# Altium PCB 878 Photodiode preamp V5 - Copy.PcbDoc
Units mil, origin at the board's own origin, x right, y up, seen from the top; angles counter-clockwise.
Board outline 4488 x 4488 mil, 6 copper layers (Top Layer, Internal Plane 1, Dummy Ground, Dummy Power, Internal Plane 2, Bottom Layer), stack 21.034 mil thick; 182 components, 80 nets, 485 pads, 78 vias.
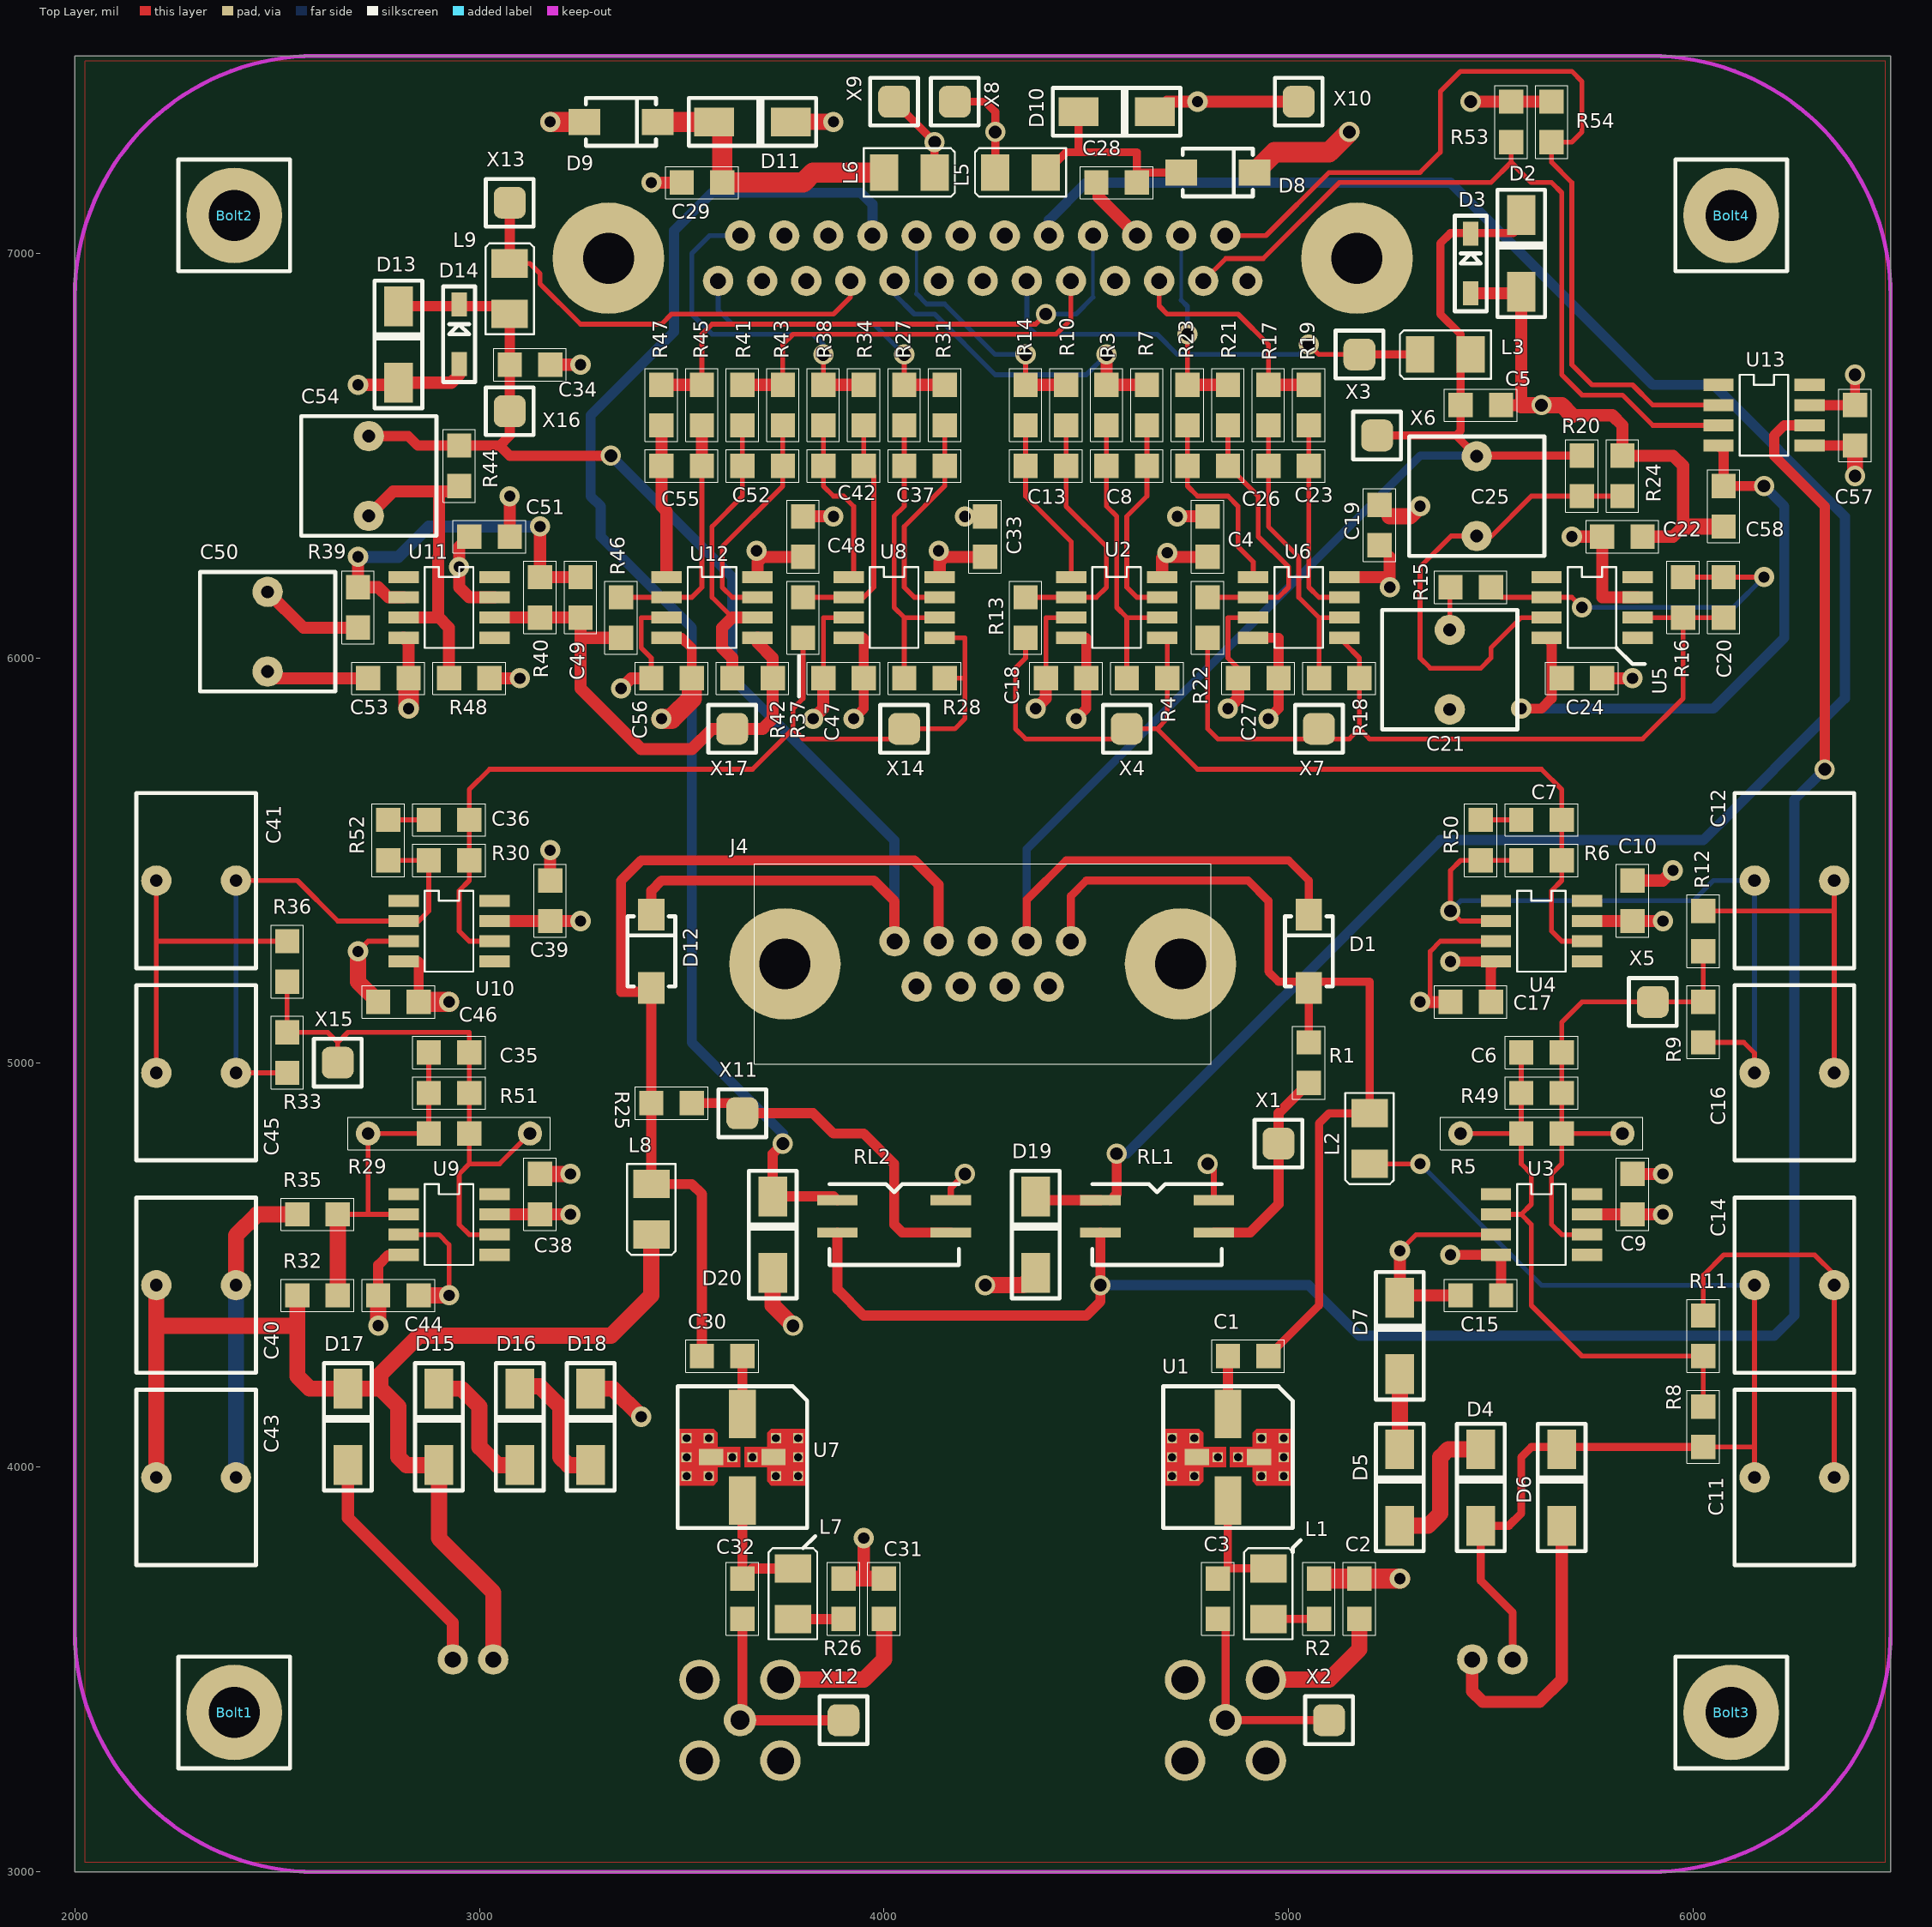
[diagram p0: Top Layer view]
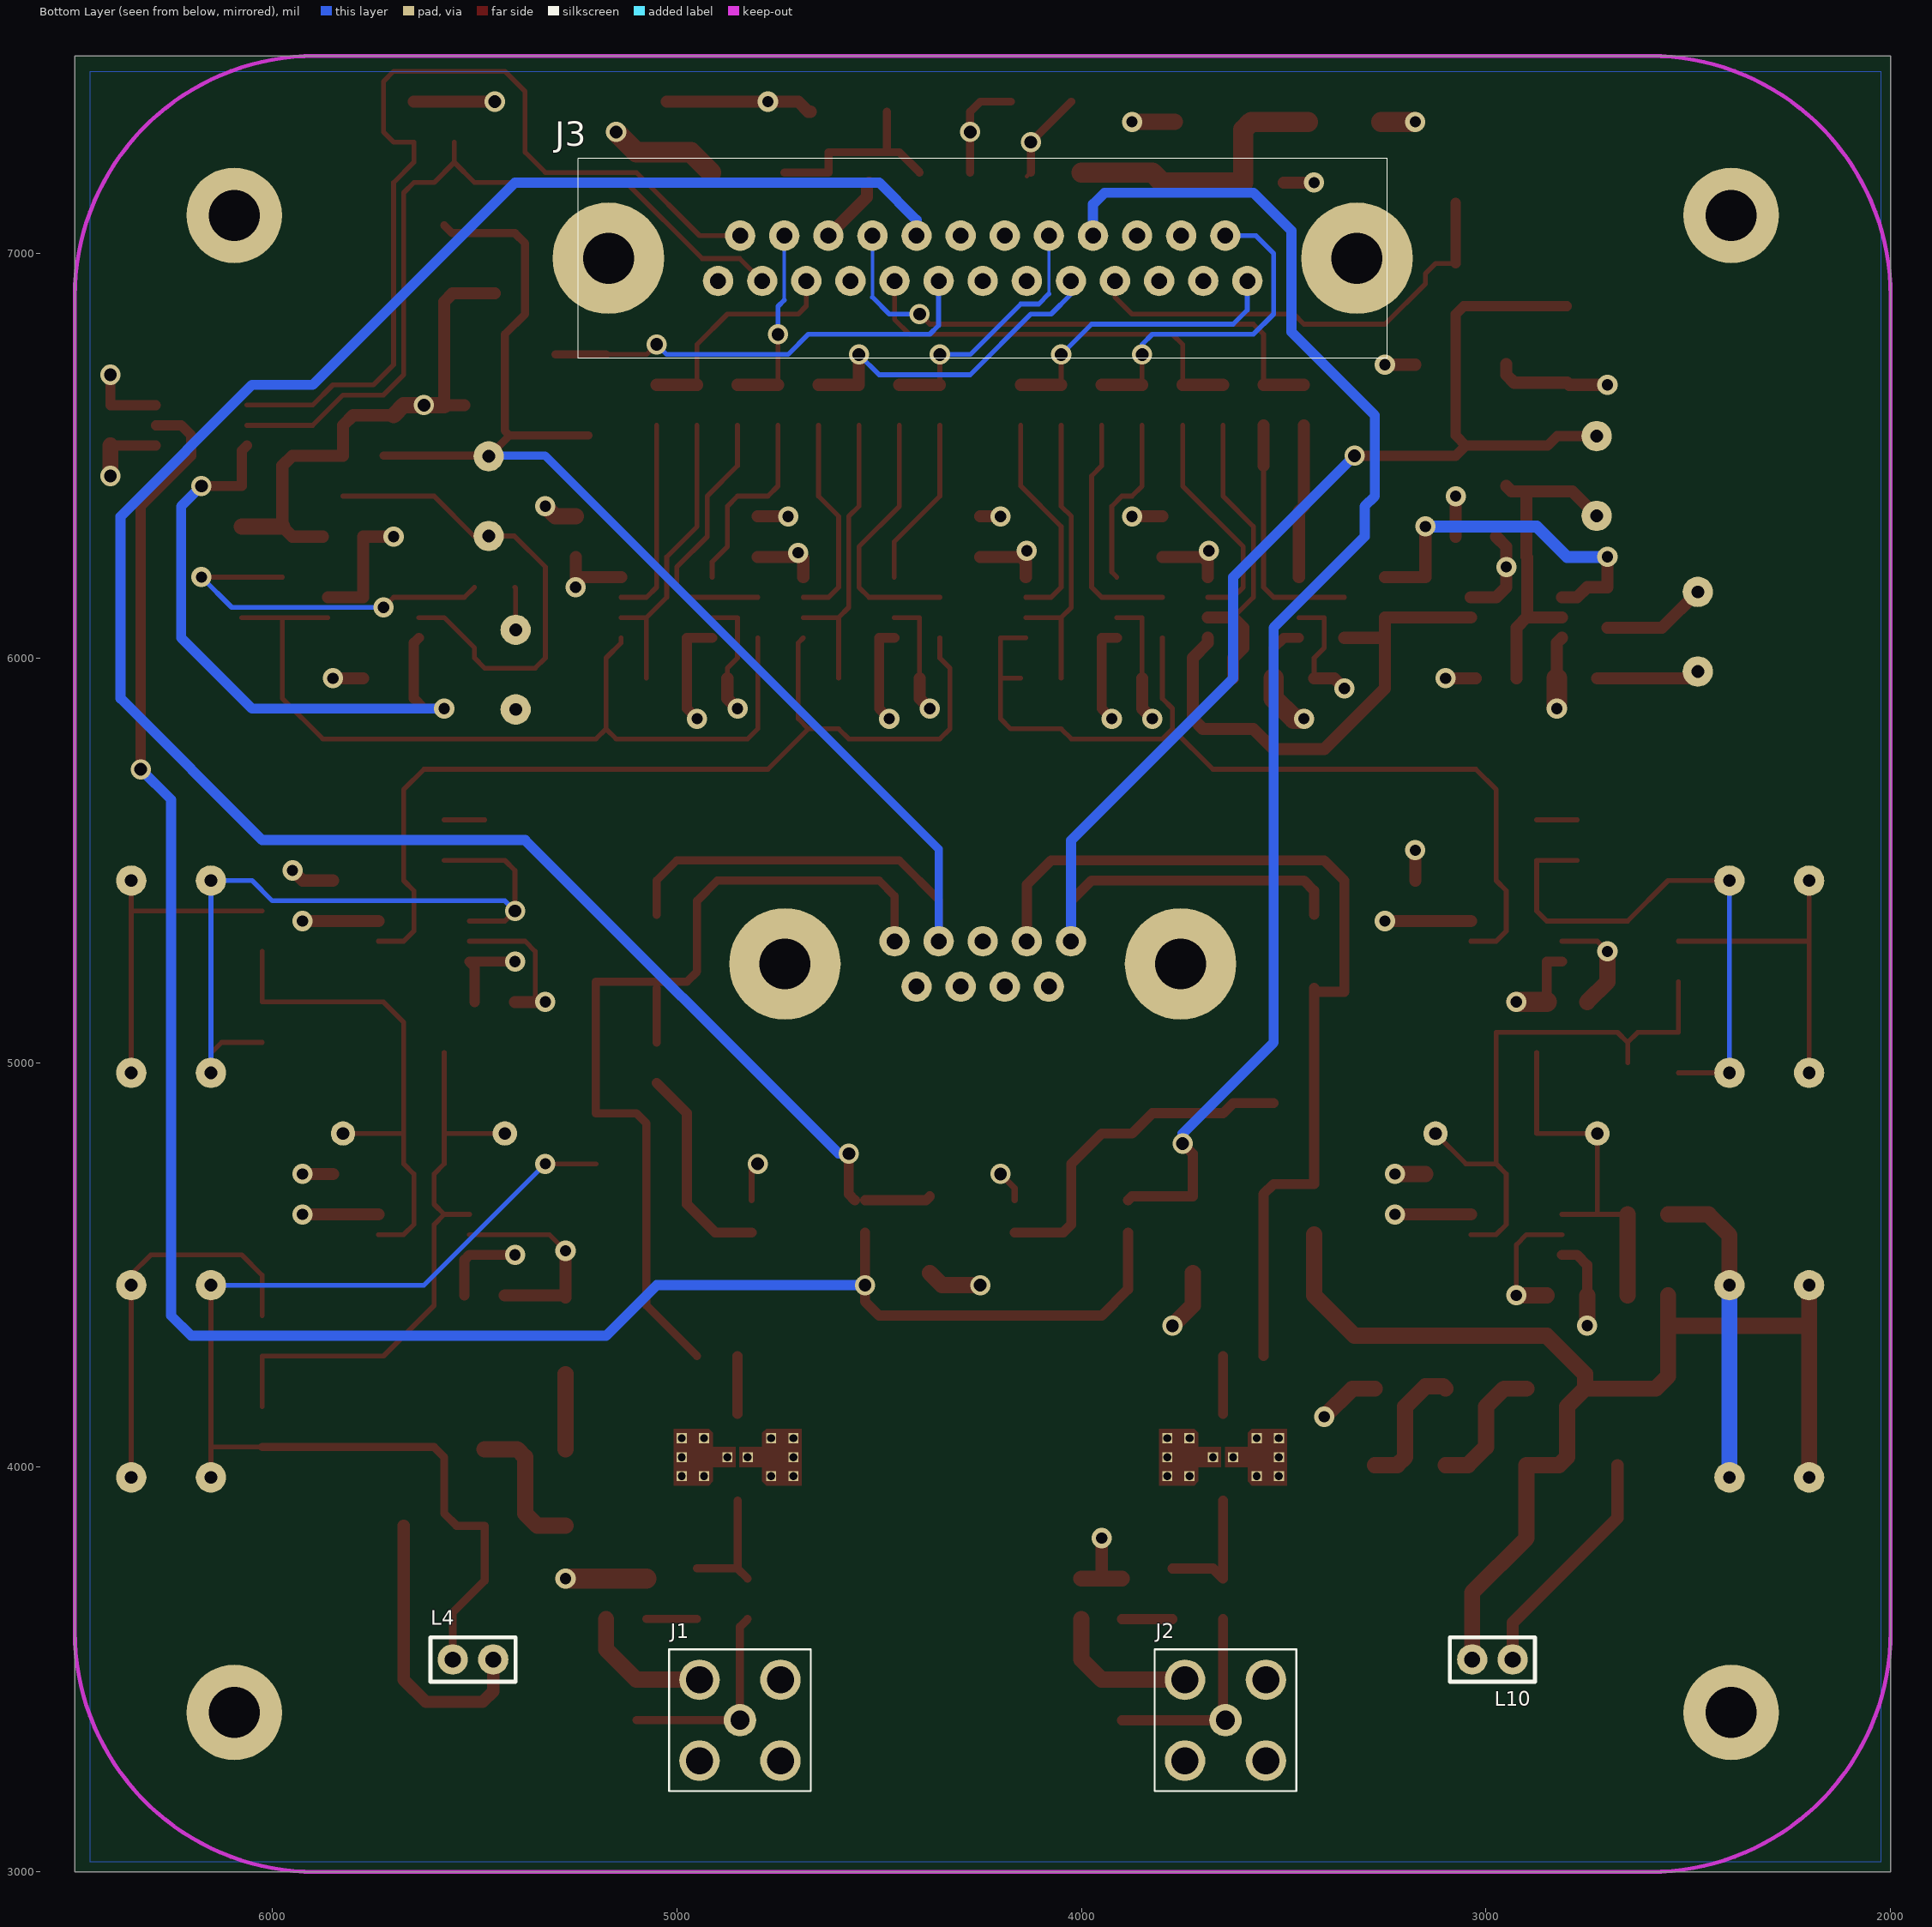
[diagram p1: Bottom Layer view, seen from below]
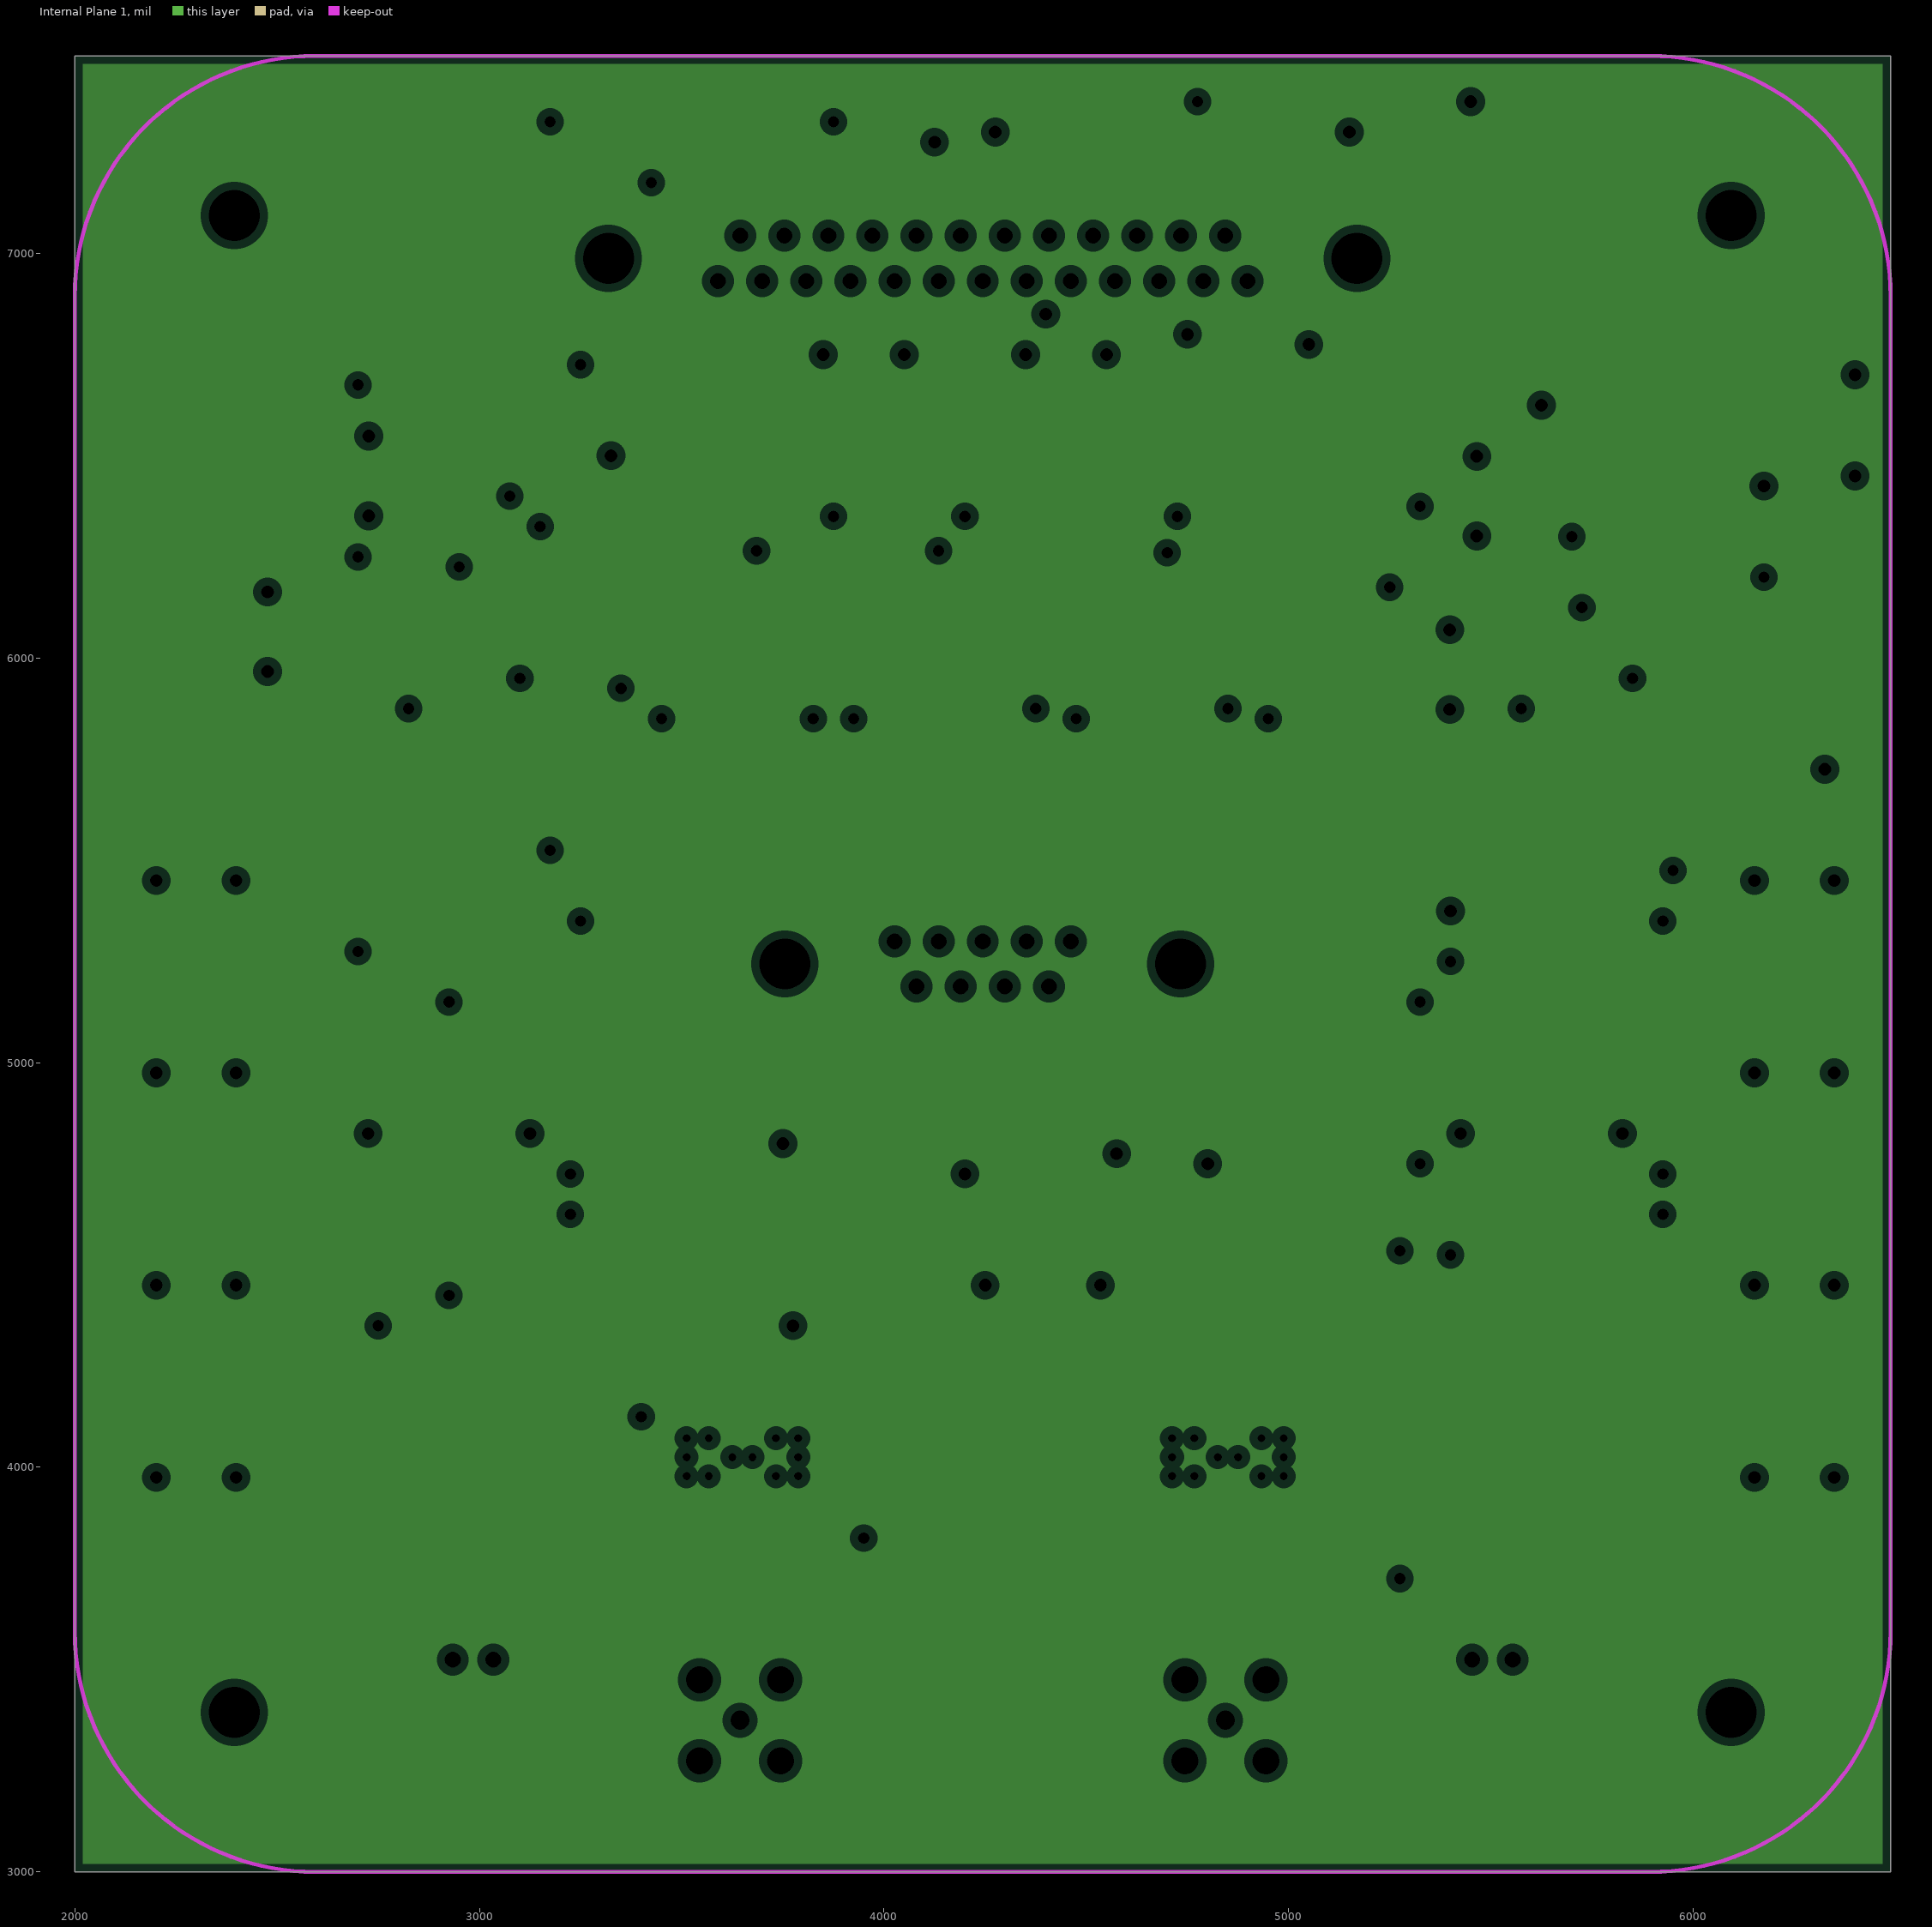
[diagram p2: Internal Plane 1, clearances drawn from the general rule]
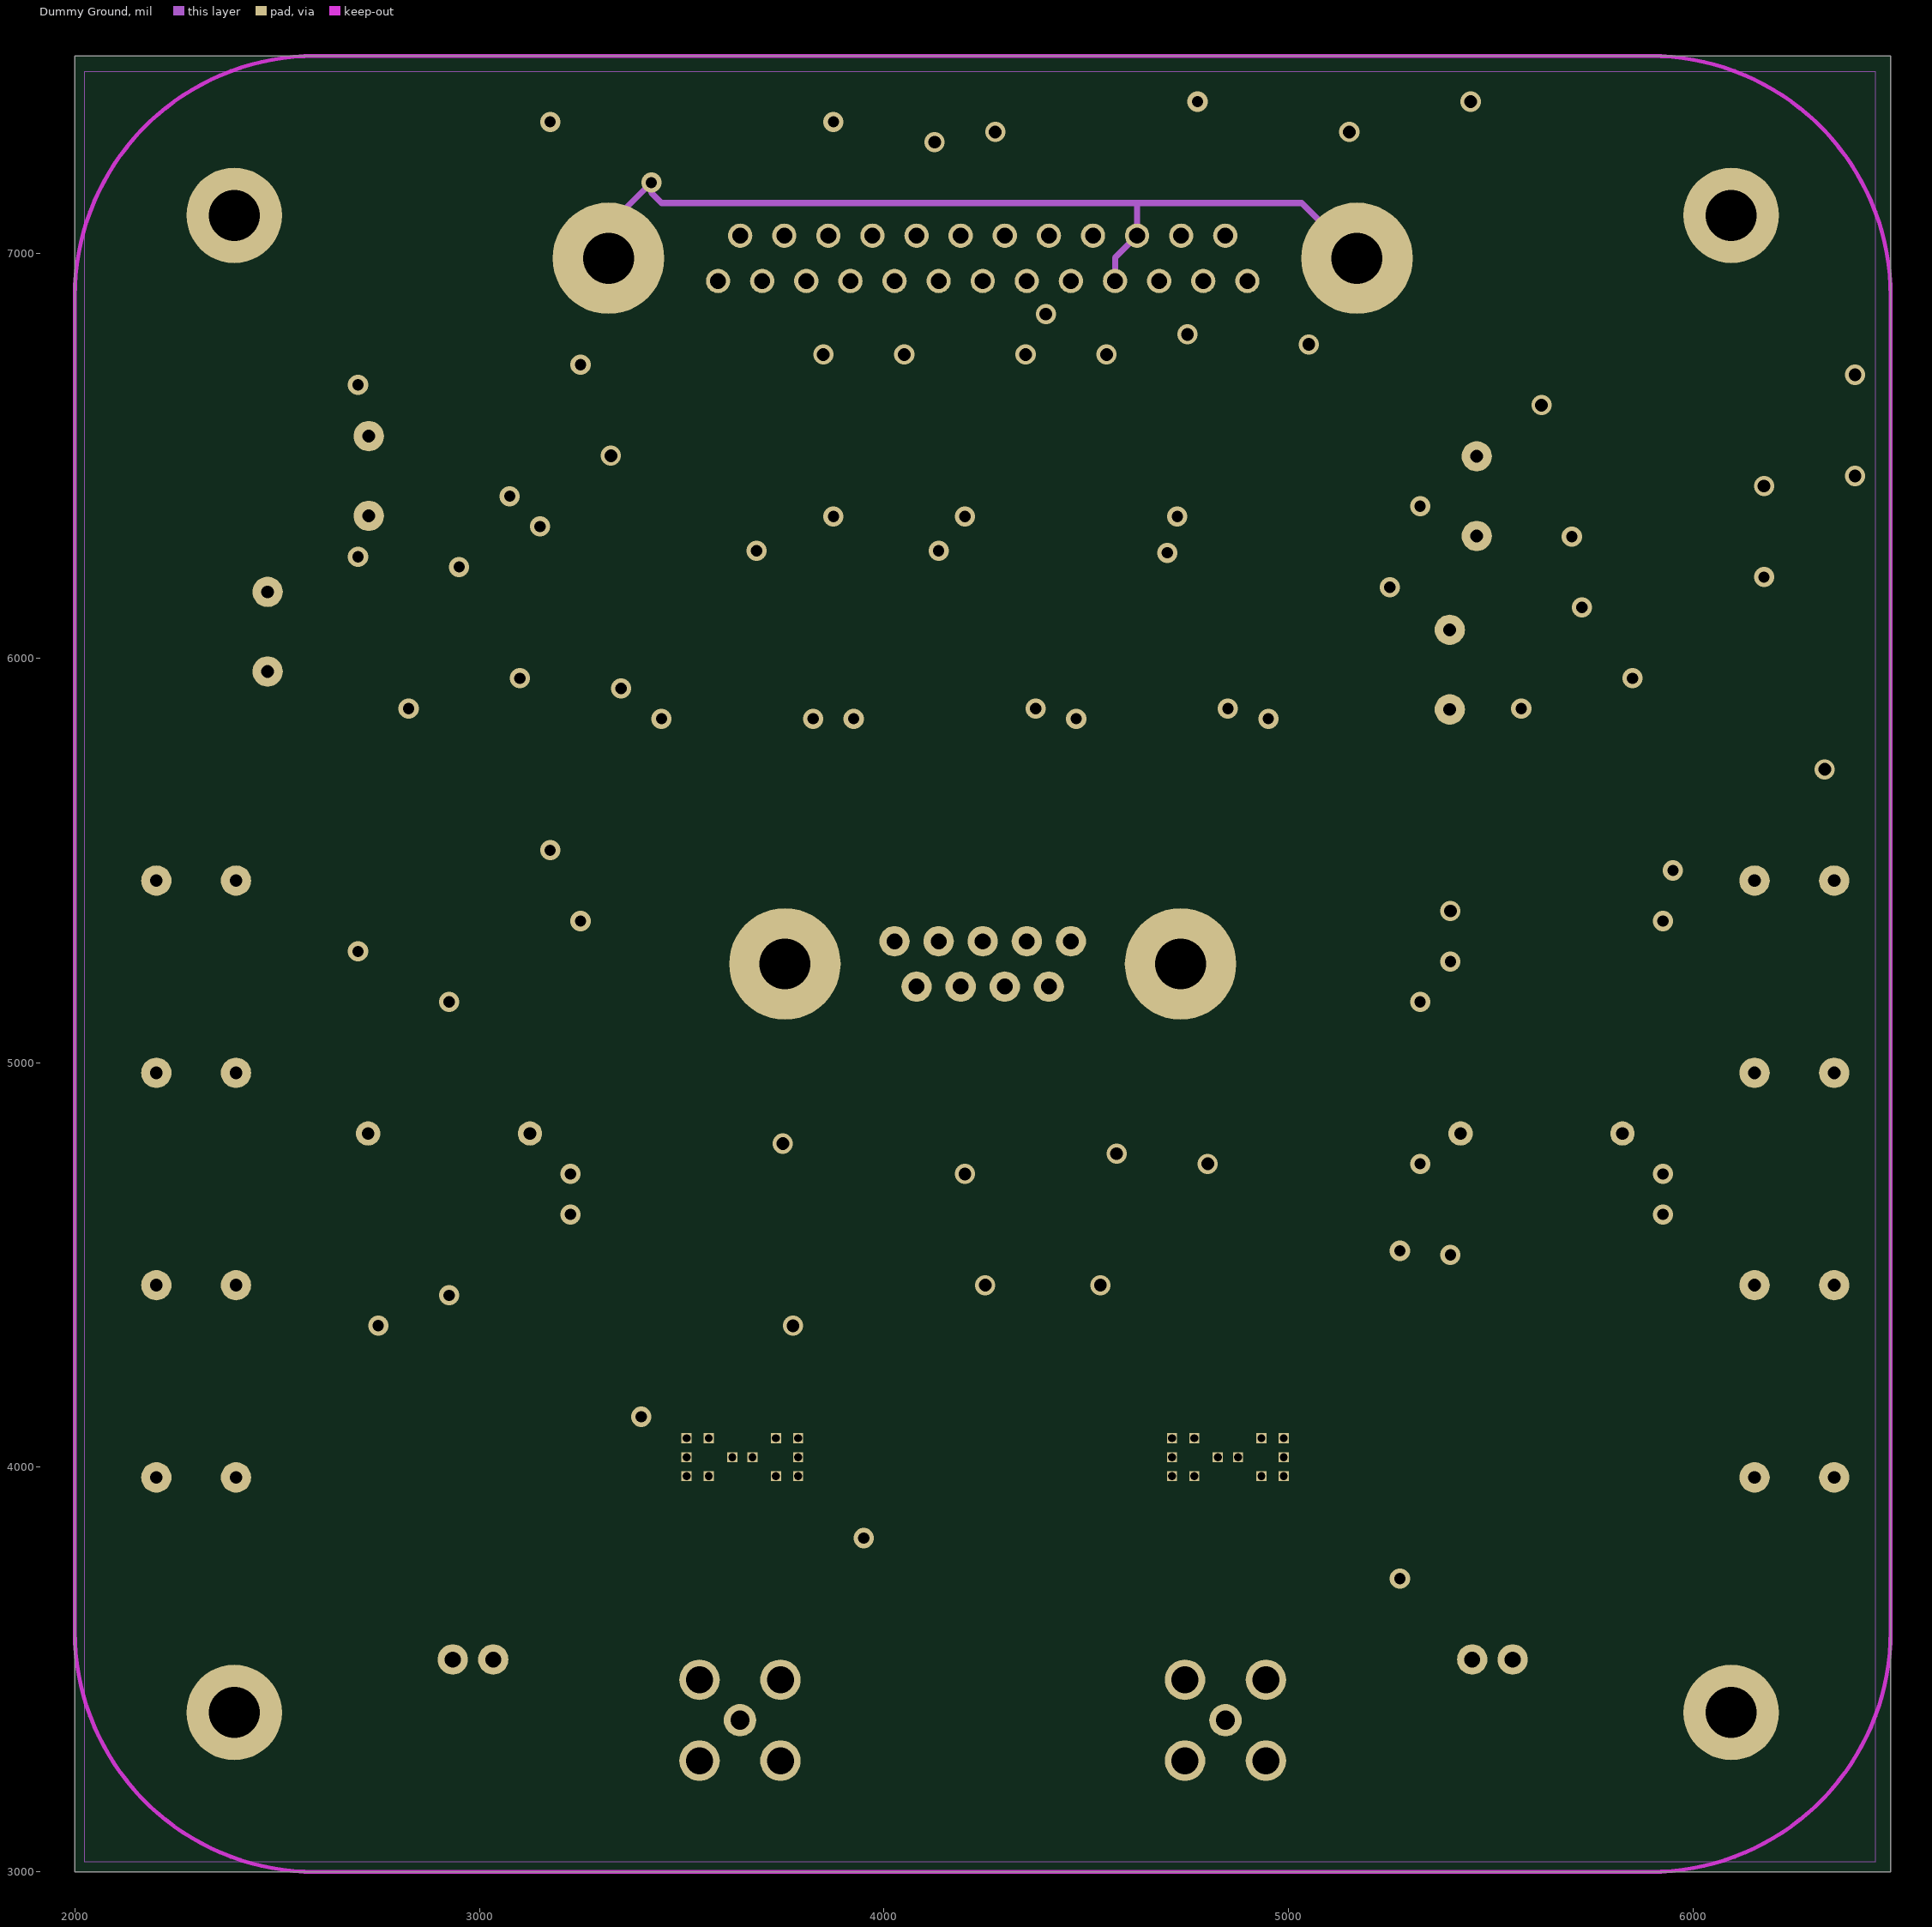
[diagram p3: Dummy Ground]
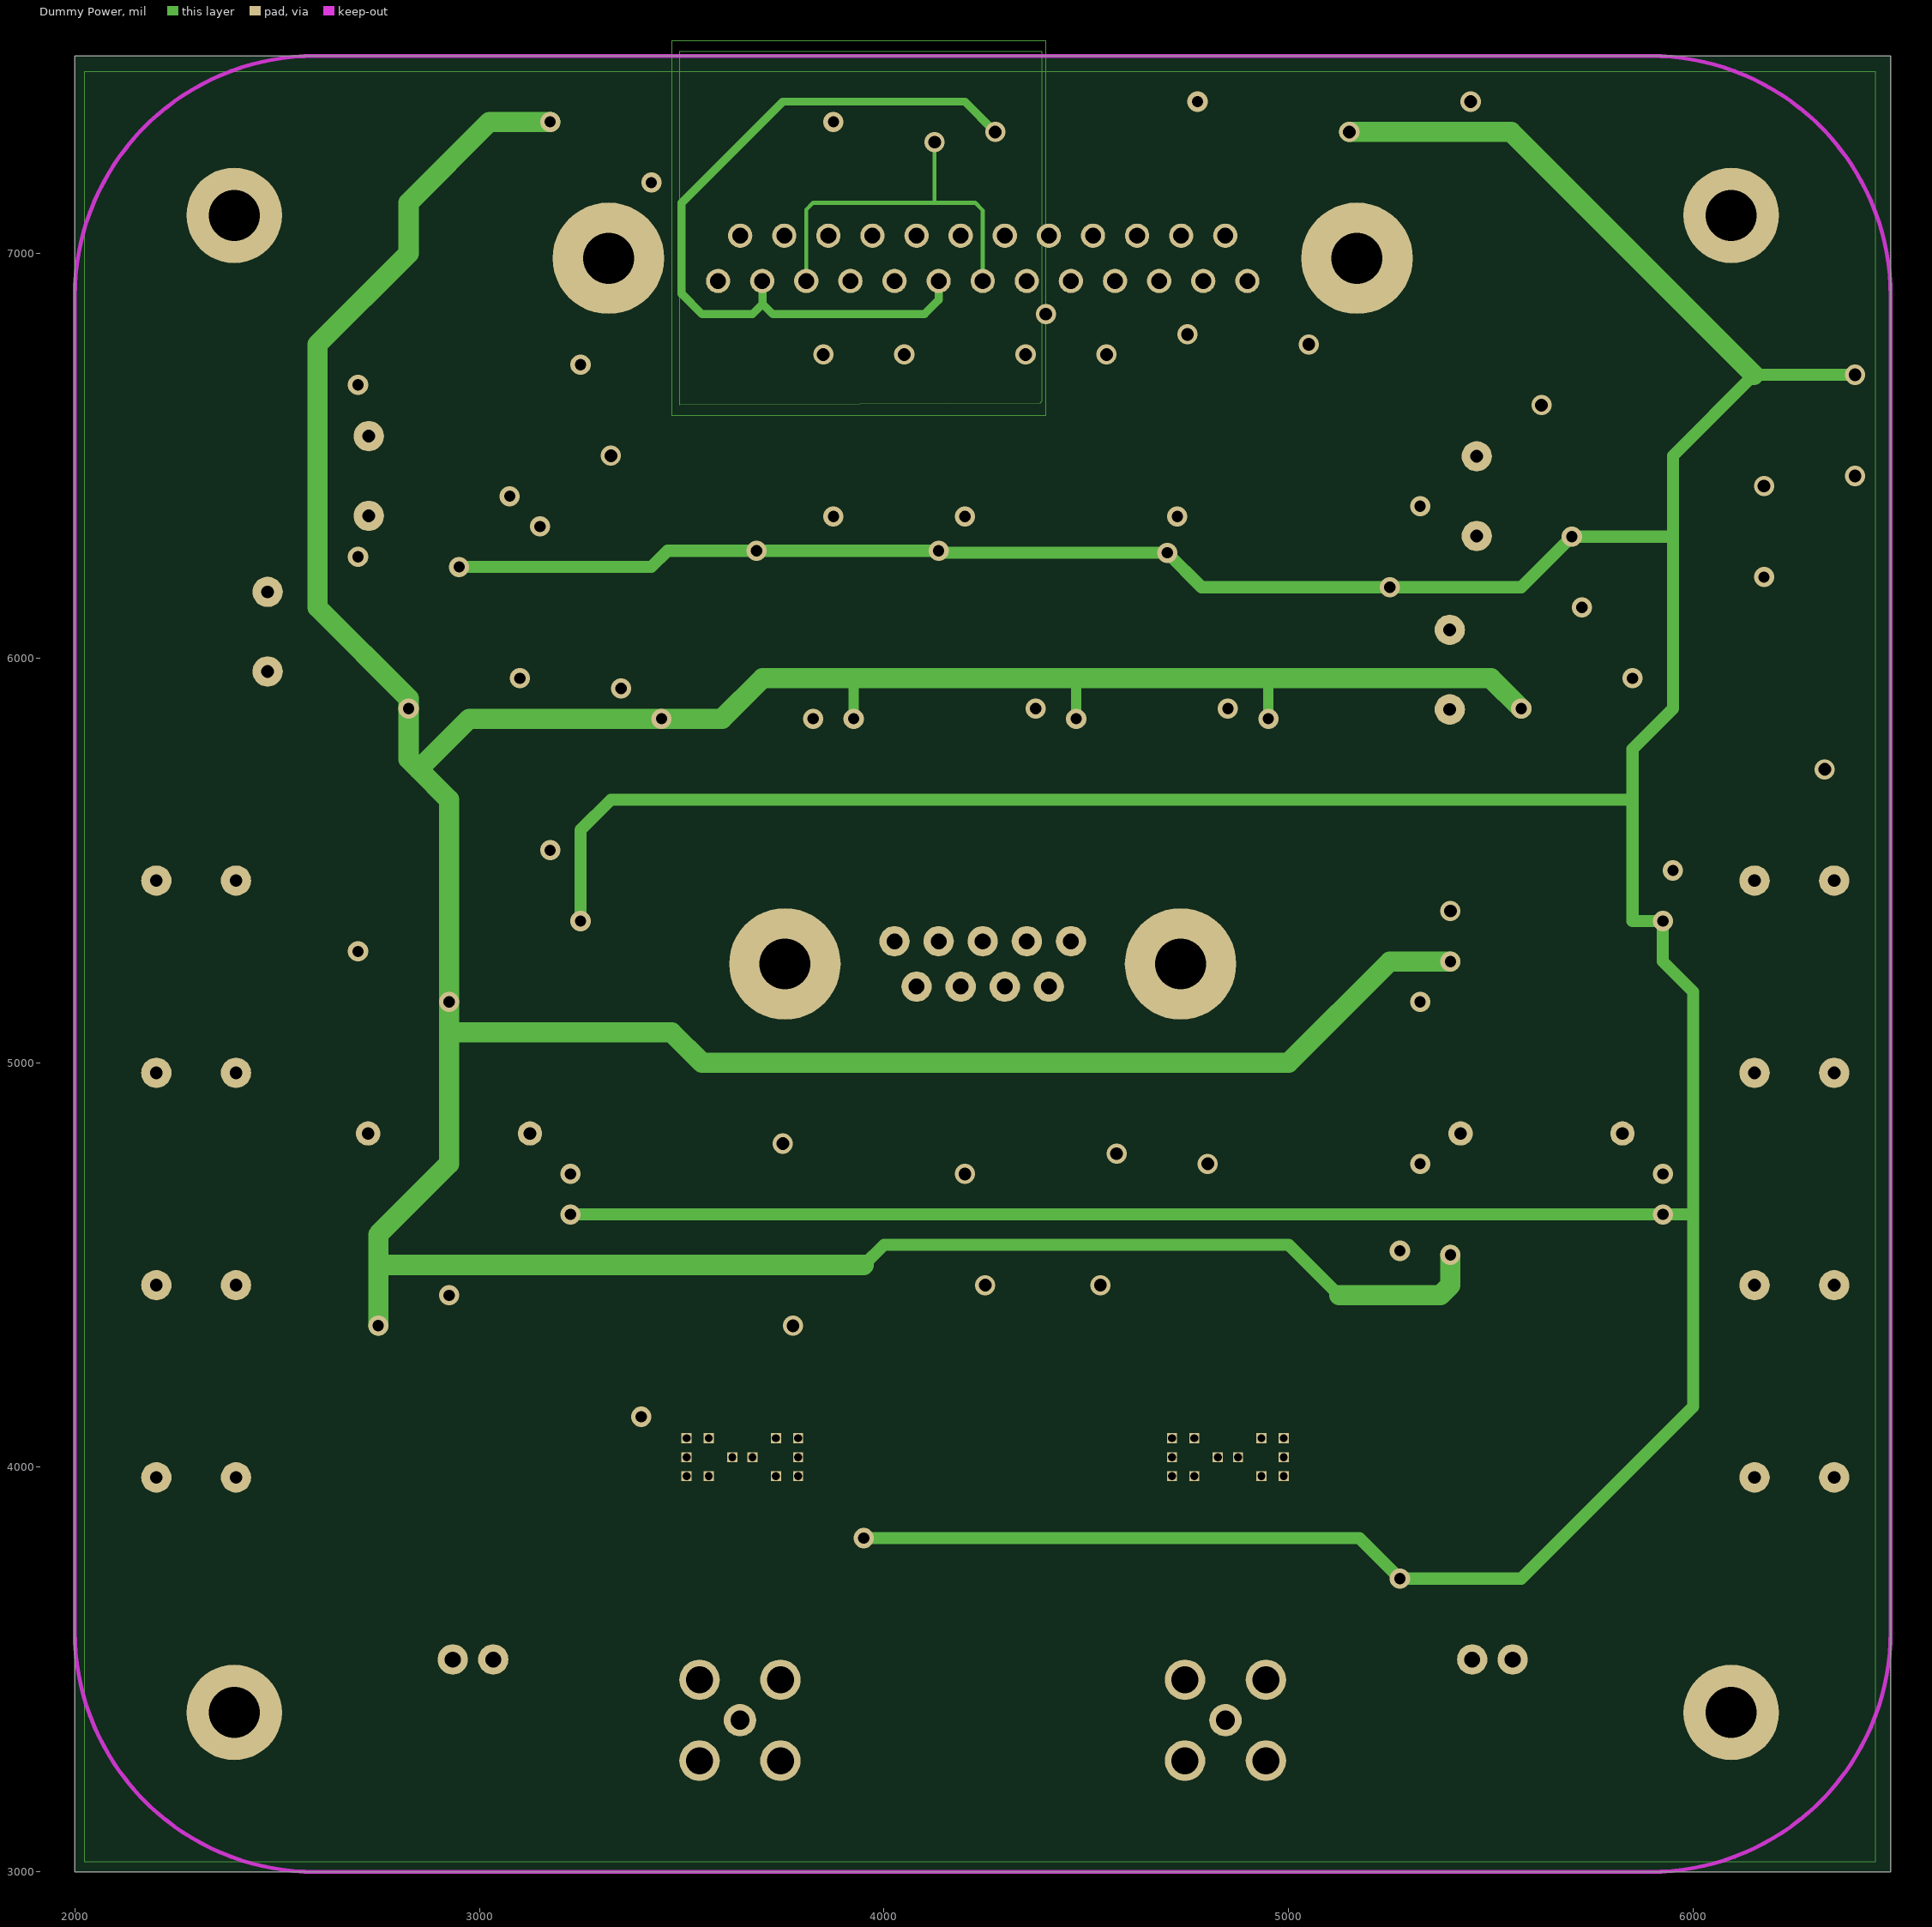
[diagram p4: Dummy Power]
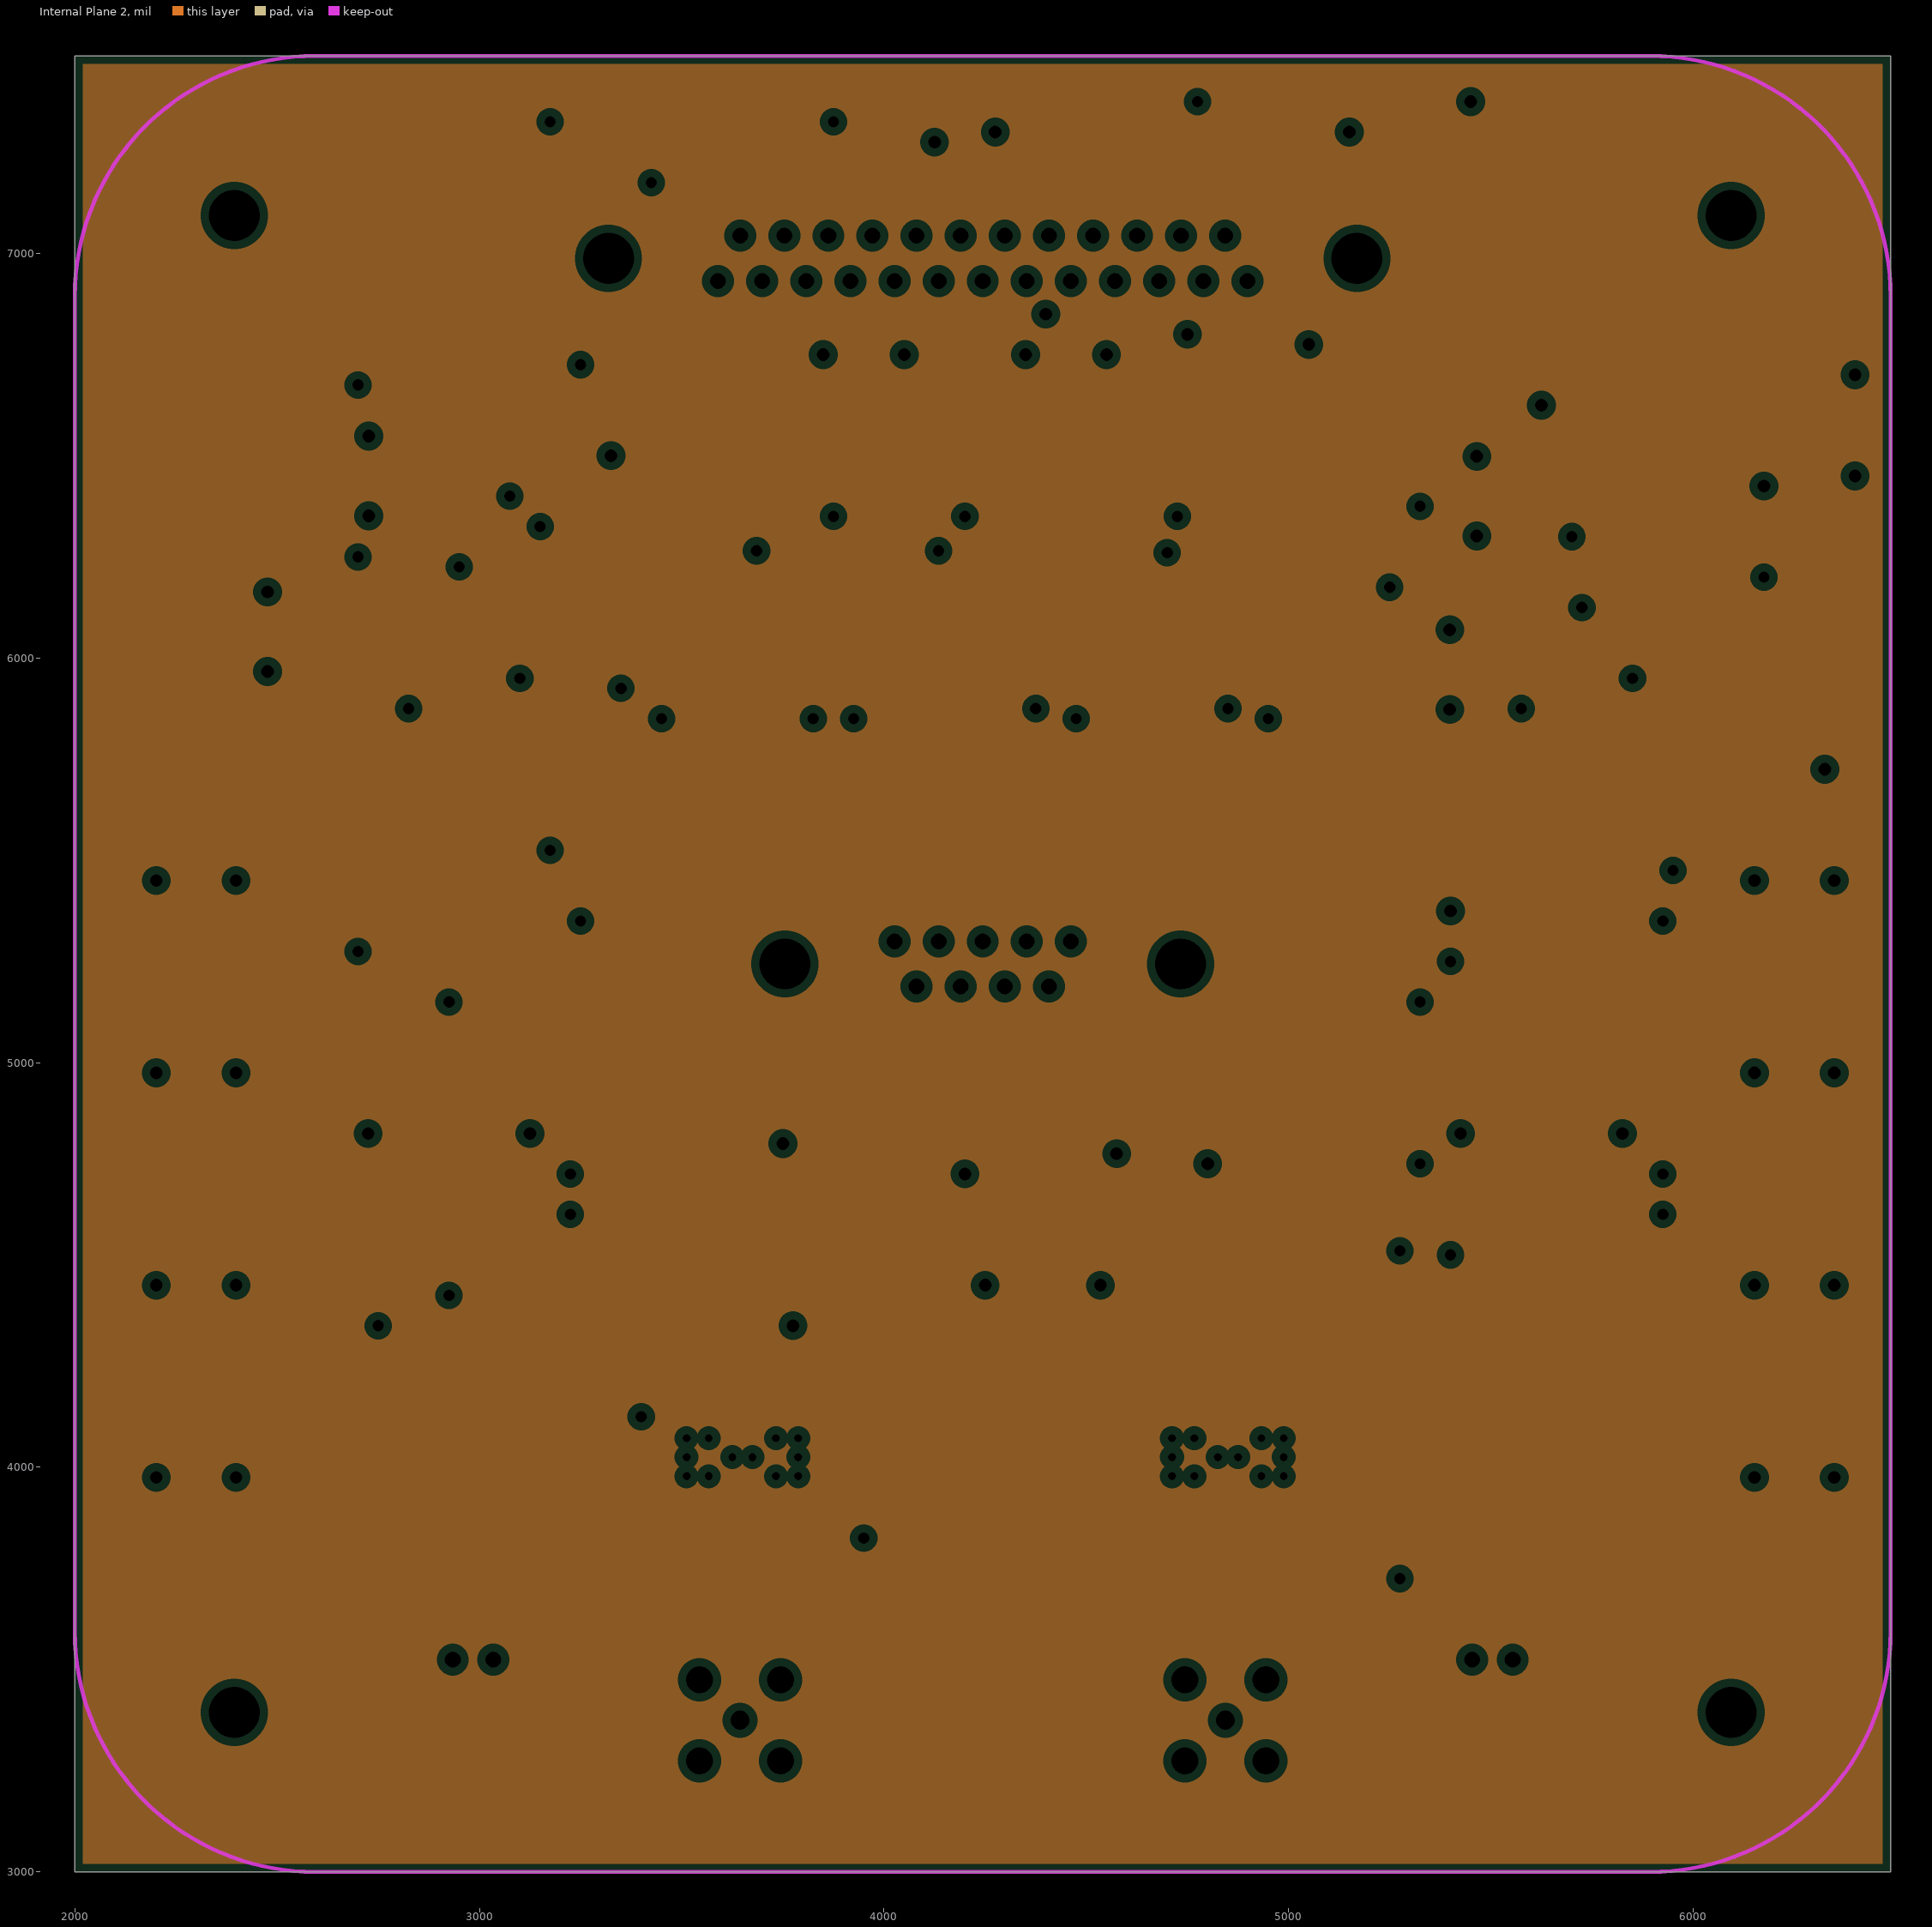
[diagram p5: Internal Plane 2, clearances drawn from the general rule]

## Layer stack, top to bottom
Top Solder: solder mask 0.4, Solder Resist, Dk 3.5
Top Layer: signal copper 1.4
Internal Plane 1: plane copper 1.4
Dummy Ground: signal copper 1.417
Dummy Power: signal copper 1.417
Internal Plane 2: plane copper 1.4
Dielectric 1: dielectric 12.6, FR-4, Dk 4.8
Bottom Layer: signal copper 1.4
Bottom Solder: solder mask 0.4, Solder Resist, Dk 3.5

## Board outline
2000,3000 6488,3000 6488,7488 2000,7488

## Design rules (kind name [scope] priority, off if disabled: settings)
Clearance Clearance_2 [InNamedPolygon('Top Layer-GND')] p1: gap=50
Clearance Clearance_1 [(InNamedPolygon('Top Layer-No Net'))] p2: gap=20
Clearance [All] p3: gap=12 except(8: Track-SMDPad)
HoleSize [All] p1: absolutevalues=TRUE maxlimit=150 minlimit=1 maxpercent=80.000 minpercent=20.000
PlaneClearance [All] p1: clearance=20
PlaneConnect [All] p1: planeconnectstyle=Relief reliefexpansion=20 reliefentries=4 reliefconductorwidth=10 reliefairgap=10
PolygonConnect [All] p1: connectstyle=Relief reliefconductorwidth=10 reliefentries=4 polygonreliefangle="90 Angle" airgapwidth=10
RoutingVias [All] p1: holewidth=31.5 width=50 viastyle="Through Hole" minholewidth=19.68 minwidth=30 maxholewidth=31.5 maxwidth=60
SilkToSilkClearance [All] p1: silktosilkclearance=5
SilkToSolderMaskClearance [IsPad] p1: minsilkscreentomaskgap=3 clearancetoexposedcopper=TRUE
SolderMaskExpansion [All] p1: expansion=4
Width [All] p1: maxlimit=200 minlimit=6 preferedwidth=12
25 further rules are at their usual default settings.

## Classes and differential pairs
component class "878 Photodiode preamp v5 P2": C30 C31 C32 C33 C34 C35 C36 C37 C38 C39 C40 C41 C42 C43 C44 C45 C46 C47 C48 C49 C50 C51 C52 C53 C54 C55 C56 D12 D13 D14 D15 D16 D17 D18 D20 J2 J3 J4 L7 L8 L9 L10 R25 R26 R27 R28 R29 R30 R31 R32 R33 R34 R35 R36 R37 R38 R39 R40 R41 R42 R43 R44 R45 R46 R47 R48 R51 R52 RL2 U7 U8 U9 U10 U11 U12 X11 X12 X13 X14 X15 X16 X17
component class "878 Photodiode preamp v5 P1": Bolt1 Bolt2 Bolt3 Bolt4 C1 C2 C3 C4 C5 C6 C7 C8 C9 C10 C11 C12 C13 C14 C15 C16 C17 C18 C19 C20 C21 C22 C23 C24 C25 C26 C27 C28 C29 C57 C58 D1 D2 D3 D4 D5 D6 D7 D8 D9 D10 D11 D19 J1 L1 L2 L3 L4 L5 L6 R1 R2 R3 R4 R5 R6 R7 R8 R9 R10 R11 R12 R13 R14 R15 R16 R17 R18 R19 R20 R21 R22 R23 R24 R49 R50 R53 R54 RL1 U1 U2 U3 U4 U5 U6 U13 X1 X2 X3 X4 X5 X6 X7 X8 X9 X10

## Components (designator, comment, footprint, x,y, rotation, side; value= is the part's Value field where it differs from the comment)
Bolt1 "Bolt M3" BOLT 2394,3394 r0 top
Bolt2 "Bolt M3" BOLT 2394,7094 r0 top
Bolt3 "Bolt M3" BOLT 6094,3394 r0 top
Bolt4 "Bolt M3" BOLT 6094,7094 r0 top
C1 "Cap200" HS0805Long 4900,4275 r180 top
C2 "Cap200" HS0805Long 5175,3675 r270 top
C3 "Cap200" HS0805Long 4825,3675 r270 top
C4 "Cap200" HS0805Long 4800,6300 r90 top
C5 "Cap200" HS0805Long 5475,6625 r0 top
C6 "Cap200" HS0805Long 5625,5025 r0 top
C7 "Cap200" HS0805Long 5625,5600 r0 top
C8 "Cap200" HS0805Long 4600,6475 r0 top
C9 "Cap200" HS0805Long 5850,4675 r90 top
C10 "Cap200" HS0805Long 5850,5400 r90 top
C11 "Cap200" "MKS2 7.2 11" 6250,3975 r0 top
C12 "Cap200" "MKS2 7.2 11" 6250,5450 r180 top
C13 "Cap200" HS0805Long 4400,6475 r180 top
C14 "Cap200" "MKS2 7.2 11" 6250,4450 r0 top
C15 "Cap200" HS0805Long 5475,4425 r180 top
C16 "Cap200" "MKS2 7.2 11" 6250,4975 r180 top
C17 "Cap200" HS0805Long 5450,5150 r180 top
C18 "Cap200" HS0805Long 4450,5950 r180 top
C19 "Cap200" HS0805Long 5225,6328.51 r90 top
C20 "Cap200" HS0805Long 6075,6150 r270 top
C21 "Cap200" "MKS2 7.2 8.5" 5398.33,5971.35 r90 top
C22 "Cap200" HS0805Long 5825,6300 r0 top
C23 "Cap200" HS0805Long 5000,6475 r0 top
C24 "Cap200" HS0805Long 5725,5950 r0 top
C25 "Cap200" "MKS2 7.2 8.5" 5465.07,6400 r270 top
C26 "Cap200" HS0805Long 4800,6475 r180 top
C27 "Cap200" HS0805Long 4925,5950 r180 top
C28 "Cap200" HS0805Long 4575,7175 r180 top
C29 "Cap200" HS0805Long 3550,7175 r180 top
C30 "Cap200" HS0805Long 3600,4275 r0 top
C31 "Cap200" HS0805Long 4000,3675 r270 top
C32 "Cap200" HS0805Long 3650,3675 r270 top
C33 "Cap200" HS0805Long 4250,6300 r90 top
C34 "Cap200" HS0805Long 3125,6725 r0 top
C35 "Cap200" HS0805Long 2925,5025 r0 top
C36 "Cap200" HS0805Long 2925,5600 r0 top
C37 "Cap200" HS0805Long 4100,6475 r0 top
C38 "Cap200" HS0805Long 3150,4675 r90 top
C39 "Cap200" HS0805Long 3175,5400 r90 top
C40 "Cap200" "MKS2 7.2 11" 2300,4450 r0 top
C41 "Cap200" "MKS2 7.2 11" 2300,5450 r0 top
C42 "Cap200" HS0805Long 3900,6475 r180 top
C43 "Cap200" "MKS2 7.2 11" 2300,3975 r0 top
C44 "Cap200" HS0805Long 2800,4425 r0 top
C45 "Cap200" "MKS2 7.2 11" 2300,4975 r0 top
C46 "Cap200" HS0805Long 2800,5150 r180 top
C47 "Cap200" HS0805Long 3900,5950 r180 top
C48 "Cap200" HS0805Long 3800,6300 r90 top
C49 "Cap200" HS0805Long 3250,6150 r270 top
C50 "Cap200" "MKS2 7.2 8.5" 2476.67,6065 r90 top
C51 "Cap200" HS0805Long 3025,6300 r0 top
C52 "Cap200" HS0805Long 3700,6475 r0 top
C53 "Cap200" HS0805Long 2775,5950 r180 top
C54 "Cap200" "MKS2 7.2 8.5" 2726.67,6449.87 r270 top
C55 "Cap200" HS0805Long 3500,6475 r180 top
C56 "Cap200" HS0805Long 3475,5950 r180 top
C57 "Cap200" HS0805Long 6400,6575 r90 top
C58 "Cap200" HS0805Long 6075,6375 r270 top
D1 "60V 1A" SMA 5050,5275 r270 top
D2 "SMAJxxCA" DO214AC 5575,7000 r270 top
D3 "60V 1A" SOD123 5450,6975 r270 top
D4 "1N4007" DO214AC 5475,3950 r270 top
D5 "1N4007" DO214AC 5275,3950 r270 top
D6 "1N4007" DO214AC 5675,3950 r270 top
D7 "1N4007" DO214AC 5275,4325 r270 top
D8 "60V 1A" SMA 4825,7200 r180 top
D9 "60V 1A" SMA 3350,7325 r180 top
D10 "SMAJxxCA" DO214AC 4575,7350 r180 top
D11 "SMAJxxCA" DO214AC 3675,7325 r180 top
D12 "60V 1A" SMA 3425,5275 r270 top
D13 "SMAJxxCA" DO214AC 2800,6775 r270 top
D14 "60V 1A" SOD123 2950,6800 r270 top
D15 "1N4007" DO214AC 2900,4100 r270 top
D16 "1N4007" DO214AC 3100,4100 r270 top
D17 "1N4007" DO214AC 2675,4100 r270 top
D18 "1N4007" DO214AC 3275,4100 r270 top
D19 "1N4004" DO214AC 4375,4575 r270 top
D20 "1N4004" DO214AC 3725,4575 r270 top
J1 "SMA" "PCB SMB" 4844,3375 r180 bottom
J2 "SMA" "PCB SMB" 3644,3375 r180 bottom
J3 "D connector 25 way" "D Socket Straight PCB 25 Way" 4244,6987.81 r0 bottom
J4 "D connector 9 way" "D Plug Straight PCB 9 Way" 4244,5244 r0 top
L1 "Inductor" HS1210 4950,3700 r270 top
L2 "Inductor" HS1210 5200,4800 r90 top
L3 "Inductor" HS1210 5375,6750 r0 top
L4 "Inductor" "2 way 0.1\"" 5503.75,3525 r0 bottom
L5 "Inductor" HS1210 4325,7200 r0 top
L6 "Inductor" HS1210 4075,7200 r180 top
L7 "Inductor" HS1210 3775,3700 r270 top
L8 "Inductor" HS1210 3425,4625 r90 top
L9 "Inductor" HS1210 3075,6925 r270 top
L10 "Inductor" "2 way 0.1\"" 2984.25,3525 r0 bottom
R1 "Res" hs0805long 5050,5000 r90 top
R2 "Res" hs0805long 5075,3675 r90 top
R3 "Res" hs0805long 4550,6625 r90 top
R4 "Res" hs0805long 4650,5950 r180 top
R5 "Res" SpecialR 5625,4825 r0 top
R6 "Res" hs0805long 5625,5500 r0 top
R7 "Res" hs0805long 4650,6625 r90 top
R8 "Res" hs0805long 6025,4100 r90 top
R9 "Res" hs0805long 6025,5100 r270 top
R10 "Res" hs0805long 4450,6625 r90 top
R11 "Res" hs0805long 6025,4325 r270 top
R12 "Res" hs0805long 6025,5325 r90 top
R13 "Res" hs0805long 4350,6100 r90 top
R14 "Res" hs0805long 4350,6625 r90 top
R15 "Res" hs0805long 5450,6175 r180 top
R16 "Res" hs0805long 5975,6150 r270 top
R17 "Res" hs0805long 4950,6625 r90 top
R18 "Res" hs0805long 5125,5950 r180 top
R19 "Res" hs0805long 5050,6625 r90 top
R20 "Res" hs0805long 5725,6450 r90 top
R21 "Res" hs0805long 4850,6625 r90 top
R22 "Res" hs0805long 4800,6100 r90 top
R23 "Res" hs0805long 4750,6625 r90 top
R24 "Res" hs0805long 5825,6450 r270 top
R25 "Res" hs0805long 3475,4900 r180 top
R26 "Res" hs0805long 3900,3675 r90 top
R27 "Res" hs0805long 4050,6625 r90 top
R28 "Res" hs0805long 4100,5950 r180 top
R29 "Res" SpecialR 2925,4825 r0 top
R30 "Res" hs0805long 2925,5500 r0 top
R31 "Res" hs0805long 4150,6625 r90 top
R32 "Res" hs0805long 2600,4425 r0 top
R33 "Res" hs0805long 2525,5025 r270 top
R34 "Res" hs0805long 3950,6625 r90 top
R35 "Res" hs0805long 2600,4625 r0 top
R36 "Res" hs0805long 2525,5250 r90 top
R37 "Res" hs0805long 3800,6100 r90 top
R38 "Res" hs0805long 3850,6625 r90 top
R39 "Res" hs0805long 2700,6125 r270 top
R40 "Res" hs0805long 3150,6150 r270 top
R41 "Res" hs0805long 3650,6625 r90 top
R42 "Res" hs0805long 3675,5950 r180 top
R43 "Res" hs0805long 3750,6625 r90 top
R44 "Res" hs0805long 2950,6475 r90 top
R45 "Res" hs0805long 3550,6625 r90 top
R46 "Res" hs0805long 3350,6100 r90 top
R47 "Res" hs0805long 3450,6625 r90 top
R48 "Res" hs0805long 2975,5950 r180 top
R49 "Res" hs0805long 5625,4925 r0 top
R50 "Res" hs0805long 5475,5550 r90 top
R51 "Res" hs0805long 2925,4925 r0 top
R52 "Res" hs0805long 2775,5550 r90 top
R53 "Res" HS0805Long 5550,7325 r270 top
R54 "Res" HS0805Long 5650,7325 r270 top
RL1 "9901 relay" "9901 Relay" 4675,4600 r0 top
RL2 "9901 relay" "9901 Relay" 4025,4600 r0 top
U1 "MAR-6SM" ww107 4850,4025 r180 top
U2 "AD8672ARZ" "SOIC 8" 4575,6125 r270 top
U3 "LT1028" "SOIC 8" 5625,4600 r270 top
U4 "LT1028" "SOIC 8" 5625,5325 r270 top
U5 "LT1028" "SOIC 8" 5750,6125 r270 top
U6 "AD8672ARZ" "SOIC 8" 5025,6125 r270 top
U7 "MAR-6SM" ww107 3650,4025 r180 top
U8 "AD8672ARZ" "SOIC 8" 4025,6125 r270 top
U9 "LT1028" "SOIC 8" 2925,4600 r270 top
U10 "LT1028" "SOIC 8" 2925,5325 r270 top
U11 "LT1028" "SOIC 8" 2925,6125 r270 top
U12 "AD8672ARZ" "SOIC 8" 3575,6125 r270 top
U13 "AD620" "SOIC 8" 6175,6600 r270 top
X1 "TestPoint" "SM Test point" 4975,4800 r0 top
X2 "TestPoint" "SM Test point" 5100,3375 r0 top
X3 "TestPoint" "SM Test point" 5175,6750 r90 top
X4 "TestPoint" "SM Test point" 4600,5825 r90 top
X5 "TestPoint" "SM Test point" 5900,5150 r90 top
X6 "TestPoint" "SM Test point" 5218.68,6550 r0 top
X7 "TestPoint" "SM Test point" 5075,5825 r0 top
X8 "TestPoint" "SM Test point" 4175,7375 r0 top
X9 "TestPoint" "SM Test point" 4025,7375 r0 top
X10 "TestPoint" "SM Test point" 5025,7375 r0 top
X11 "TestPoint" "SM Test point" 3650,4875 r0 top
X12 "TestPoint" "SM Test point" 3900,3375 r0 top
X13 "TestPoint" "SM Test point" 3075,7125 r0 top
X14 "TestPoint" "SM Test point" 4050,5825 r90 top
X15 "TestPoint" "SM Test point" 2650,5000 r90 top
X16 "TestPoint" "SM Test point" 3075,6609.93 r0 top
X17 "TestPoint" "SM Test point" 3625,5825 r0 top

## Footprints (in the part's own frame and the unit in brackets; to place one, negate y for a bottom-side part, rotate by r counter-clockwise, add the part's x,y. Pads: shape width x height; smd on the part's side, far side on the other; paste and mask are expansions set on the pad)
"2 way 0.1\"" [mm] "two wire component!"
  round 1.905 hole 1: 1(-1.27,0) 2(1.27,0)
  silkscreen extent -2.67,-1.4 2.67,1.4
"9901 Relay" [mil] "SM reed relay"
  rect 100x25 smd: 1(-140,60) 2(140,60) 5(-140,-20) 6(140,-20)
  silkscreen extent -160,-100 160,100
BOLT [mm] "M3 mounting bolt"
  round 6 hole 3.2: 1(0,0)
  silkscreen extent -3.5,-3.5 3.5,3.5
"D Plug Straight PCB 9 Way" [mil] "D Plug Straight PCB 9 Way"
  round 75 hole 39.37: 1(-218,56) 2(-109,56) 3(0,56) 4(109,56) 5(218,56) 6(-163.5,-56) 7(-54.5,-56) 8(54.5,-56) 9(163.5,-56)
  round 275.59 hole 125.98: 10(-489,0) 10(489,0)
  silkscreen extent -564,-247 564,247
"D Socket Straight PCB 25 Way" [mil] "D socket Straight PCB 25 Way"
  round 75 / inner round 60 / far side round 75 hole 39.37: 1(654,56) 2(545,56) 3(436,56) 4(327,56) 5(218,56) 6(109,56) 7(0,56) 8(-109,56) 9(-218,56) 10(-327,56) 11(-436,56) 12(-545,56) 13(-654,56) 14(599.5,-56) 15(490.5,-56) 16(381.5,-56) 17(272.5,-56) 18(163.5,-56) 19(54.5,-56) 20(-54.5,-56) 21(-163.5,-56) 22(-272.5,-56) 23(-381.5,-56) 24(-490.5,-56) 25(-599.5,-56)
  round 275.59 hole 125.98: 26(-925,0) 26(925,0)
  silkscreen extent -1000,-247 1000,247
DO214AC [mm] "DO214AC"
  rect 2.5x1.8 smd: 1(-2.4,0) 2(2.4,0)
  silkscreen extent -4,-1.5 4,1.5
HS0805Long [mil] "0805 on big pads for hand soldering will also take 1206"
  rect 60x60 smd: 1(-50,0) 2(50,0)
  silkscreen extent -90,-40 90,40
hs0805long [mil] "0805 on big pads for hand soldering will also take 1206"
  rect 60x60 smd: 1(-50,0) 2(50,0)
  silkscreen extent -90,-40 90,40
HS1210 [mil] "Tant case B (A will also fit!)"
  rect 70x90 smd: 1(-50,0) 2(75,0)
  silkscreen extent -100,-60 125,60
"MKS2 7.2 8.5" [mm] "MKS2 7.2 by 8.5"
  round 1.905 hole 0.8: 1(-2.5,0) 2(2.5,0)
  silkscreen extent -3.75,-4.25 3.75,4.25
"MKS2 7.2 11" [mm] "MKS2 7.2 by 11 by 16"
  round 1.905 hole 0.8: 1(-2.5,0) 2(2.5,0)
  silkscreen extent -3.75,-5.5 3.75,5.5
"PCB SMB" [mm] "PCB mount SMB connector"
  round 2.032 hole 1.2: 1(0,0)
  round 2.54 hole 1.7: 2(-2.54,-2.54) 2(-2.54,2.54) 2(2.54,-2.54) 2(2.54,2.54)
  silkscreen extent -4.45,-4.45 4.45,4.45
"SM Test point" [mm] "SM Test point 100 x 100mil"
  rrect50% 2x2 smd: 1(0,0)
  silkscreen extent -1.5,-1.5 1.5,1.5
SMA [mm] "SMA Diode"
  rect 2x1.65 smd: 1(-2.3,0) 2(2.3,0)
  silkscreen extent -2.2,-1.5 2.2,1.5
SOD123 [mm] "SOD123 Diode (500mW Zener etc)"
  rect 1.5x0.95 smd: 1(-1.875,0) 2(1.875,0)
  silkscreen extent -3,-1 3,1
"SOIC 8" [mil] "SOIC 8"
  rect 30x75 smd: 1(-75,-112.5) 2(-25,-112.5) 3(25,-112.5) 4(75,-112.5) 5(75,112.5) 6(25,112.5) 7(-25,112.5) 8(-75,112.5)
  silkscreen extent -100,-60 100,60
SpecialR [mil] "SM or TH"
  round 60 hole 31.5: 1(-200,0) 2(200,0)
  rect 60x60 smd: 1(-50,0) 2(50,0)
  silkscreen extent -250,-40 250,40
ww107 [mil] "Mini circuits MAR-6SM"
  rect 66x120 smd: 1(0,-107) 3(0,107)
  rect 25x25 hole 19.68: 2(25,0) 2(83,-47) 2(83,47) 2(138,-47) 2(138,0) 2(138,47) 4(-138,-47) 4(-138,0) 4(-138,47) 4(-83,-47) 4(-83,47) 4(-25,0)
  rect 60x40 smd: 2(77,0) 4(-77,0)
  Top Layer region: -158,70 -158,-70 -71,-70 -61,-60 -61,-25 -5,-25 -5,25 -61,25 -61,60 -71,70
  Top Layer region: 158,70 158,-70 71,-70 61,-60 61,-25 5,-25 5,25 61,25 61,60 71,70
  silkscreen extent -160,-175 160,175

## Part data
C1 C2 C3 C4 C5 C6 C7 C8 C9 C10 C11 C12 C13 C14 C15 C16 C17 C18 C19 C20 C21 C22 C23 C24 C25 C26 C27 C28 C29 C30 C31 C32 C33 C34 C35 C36 C37 C38 C39 C40 C41 C42 C43 C44 C45 C46 C47 C48 C49 C50 C51 C52 C53 C54 C55 C56 C57 C58: "Cap 0.2\" pitch"
D1 D3 D8 D9 D12 D14: library part "Sckottky Diode"
D2 D10 D11 D13: "TVS"
D4 D5 D6 D7 D15 D16 D17 D18: library part 1N4004
J1 J2: library part "PCB SMB"
U2 U6 U8 U12: library part DualOpAmp
U3 U4 U5 U9 U10 U11: library part SingleOpAmp

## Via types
v1: diameter 50, hole 28, Top Layer to Bottom Layer, 53 vias
v2: diameter 50, hole 31.5, Top Layer to Bottom Layer, 25 vias

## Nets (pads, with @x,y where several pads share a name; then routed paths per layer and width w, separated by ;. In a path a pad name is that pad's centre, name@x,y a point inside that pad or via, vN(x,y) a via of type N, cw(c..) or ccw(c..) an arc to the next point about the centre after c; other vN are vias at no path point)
+15V: C2.1 C4.1 C9.1 C10.1 C19.1 C22.1 C31.1 C33.1 C38.1 C39.1 C48.1 C51.1 C57.2 D8.1 R2.2 R26.2 U2.8 U3.7 U4.7 U5.7 U6.8 U8.8 U9.7 U10.7 U11.7 U12.8 U13.7 | length 18134.3
  Top Layer w25: U13.7 C57.2 v2(6400,6700)
  Top Layer w30: C51.1 2950,6275 v1(2950,6225) 2950,6175 2975,6150 U11.7 ; U9.7 C38.1 v1(3225,4625) ; U10.7 C39.1 v1(3250,5350) ; U12.8 3687.5,6237.5 3700,6250 C48.1 ; 3950,3725 v1(3950,3825) ; U8.8 4137.5,6237.5 4150,6250 C33.1 ; U2.8 4687.5,6247.5 v1(4700,6260) 4710,6250 C4.1 ; U6.8 5250,6200 ; v1(5250,6175) 5250,6200 ; C19.1@5250,6250 5250,6200 ; v1(5700,6300) C22.1 5775,6150 U5.7 ; U3.7 C9.1 v1(5925,4625) ; U4.7 C10.1 v1(5925,5350)
  Top Layer w40: R26.2 3950,3725 C31.1
  Top Layer w50: D8.1 4965.55,7250 5100,7250 v2(5150,7300) ; R2.2 C2.1 v1(5275,3725)
  Dummy Power w30: v1(2950,6225) 3425,6225 3465,6265 v1(3685,6265) v1(4135,6265) 4140,6260 v1(4700,6260) 4785,6175 v1(5250,6175) 5575,6175 v1(5700,6300) 5950,6300 ; v1(3225,4625) v1(5925,4625) 6000,4625 ; v1(3250,5350) 3250,5575 3325,5650 5850,5650 ; v1(3950,3825) 5175,3825 v1(5275,3725) 5575,3725 6000,4150 6000,4625 ; v2(6400,6700) 6150,6700 5950,6500 5950,6300 ; 5850,5650 5850,5350 v1(5925,5350) 5925,5250 6000,5175 6000,4625 ; 5850,5650 5850,5775 5950,5875 5950,6300
  Dummy Power w50: v2(5150,7300) 5550,7300 6150,6700
+15VIN: J3.8 J3.12 L5.1 X8.1 | length 2189.9
  Top Layer w20: X8.1 4250,7375 4275,7350 v2(4275,7300) L5.1
  Dummy Power w20: J3.12 3700,6930.8 3700,6875 ; J3.8 4135,6885 4100,6850 3725,6850 3700,6875 ; v2(4275,7300) 4200,7375 3750,7375 3500,7125 3500,6900 3550,6850 3675,6850 3700,6875
-15V: C15.1 C17.1 C18.1 C24.1 C27.1 C44.1 C46.1 C47.1 C53.1 C56.1 C58.1 D9.2 U2.4 U3.4 U4.4 U5.4 U6.4 U8.4 U9.4 U10.4 U11.4 U12.4 U13.4 | length 15836.3
  Top Layer w25: C44.1 2750,4500 2775,4525 U9.4 ; U10.4 2850,5250 C46.1 ; U12.4 3500,6050 3525,6025 C56.1 ; U8.4 3950,6050 C47.1 3950,5875 v1(3925,5850) ; U2.4 4500,6050 C18.1 4500,5875 v1(4475,5850) ; U6.4 4975,6050 C27.1 4975,5875 v1(4950,5850) ; v1(5400,4525) U3.4 5525,4512.5 C15.1 ; v1(5400,5250) U4.4 5500,5237.5 C17.1 ; v1(5575,5875) 5625,5875 5650,5900 5650,6037.5 U5.4 ; U13.4 6075,6512.5 C58.1 v2(6175,6425)
  Top Layer w30: U11.4 2825,6037.5 C53.1
  Top Layer w40: v1(2750,4350) C44.1
  Top Layer w50: v1(2825,5875) C53.1 ; C46.1 v1(2925,5150) ; v1(3175,7325) D9.2 ; v1(3450,5850) 3475,5850 3525,5900 C56.1
  Dummy Power w25: v1(3925,5850) 3925,5950 ; v1(4475,5850) 4475,5950 ; v1(4950,5850) 4950,5950
  Dummy Power w30: 3950,4500 4000,4550 5000,4550 5125,4425
  Dummy Power w50: v1(2750,4350) 2750,4500 ; v1(3175,7325) 3025,7325 2825,7125 2825,7000 2600,6775 2600,6125 2825,5900 v1(2825,5875) 2825,5750 2850,5725 ; 3950,4500 2750,4500 ; 5125,4425 5375,4425 5400,4450 v1(5400,4525) ; v1(5400,5250) 5250,5250 5000,5000 3550,5000 3475,5075 2925,5075 ; v1(5575,5875) 5500,5950 4950,5950 4475,5950 3925,5950 3700,5950 3600,5850 v1(3450,5850) 2975,5850 2850,5725 ; 2750,4500 2750,4575 2925,4750 2925,5075 ; 2850,5725 2925,5650 v1(2925,5150) 2925,5075
  Bottom Layer w25: v1(5575,5875) 6050,5875 6225,6050 6225,6375 v2(6175,6425)
-15VIN: J3.7 J3.11 L6.1 X9.1 | length 1181.9
  Top Layer w10: L6.1 L6.1@4135,7190
  Top Layer w20: X9.1 v2(4125,7275) L6.1
  Dummy Power w10: J3.11 3808,7108 3825,7125 4125,7125 ; v2(4125,7275) 4125,7125 ; J3.7 4244,7106 4225,7125 4125,7125
BIASIN1: J3.6 L3.1 X3.1 | length 1107.3
  Top Layer w12: v2(5050,6775) 5075,6750 X3.1
  Top Layer w20: X3.1 L3.1@5300,6750
  Bottom Layer w12: J3.6 4353,6822 4375,6800 4675,6800 4725,6750 5025,6750 v2(5050,6775)
BIASIN2: J3.10 L9.1 X13.1 | length 1136.3
  Top Layer w12: L9.1 3125,6975 3150,6950 3150,6925 3250,6825 3450,6825 3475,6850 3875,6850 3917,6892 J3.10
  Top Layer w25: L9.1 X13.1
BIASMON1+: J3.3 R17.2 R19.2 | length 571.2
  Top Layer w12: J3.3 4680,6870 4700,6850 4875,6850 4950,6775 R17.2
  Top Layer w30: R17.2 R19.2
BIASMON1-: J3.15 R21.2 R23.2 | length 475.2
  Top Layer w12: R23.2 v2(4750,6800)
  Top Layer w30: R23.2 R21.2
  Bottom Layer w8: 4734.5,6884.5 J3.15
  Bottom Layer w12: 4734.5,6884.5 4750,6869 v2(4750,6800)
BIASMON2+: J3.5 R41.2 R43.2 | length 1032.5
  Top Layer w12: R43.2 3750,6775 3775,6800 4425,6800 4462,6837 J3.5
  Top Layer w30: R41.2 R43.2
BIASMON2-: J3.17 R45.2 R47.2 | length 1381.7
  Top Layer w12: R45.2 3550,6800 3575,6825 4375,6825 v2(4400,6850)
  Top Layer w30: R47.2 R45.2
  Bottom Layer w8: 4516.5,6891.5 J3.17
  Bottom Layer w12: v2(4400,6850) 4475,6850 4516.5,6891.5
GND: Bolt1.1 Bolt2.1 Bolt3.1 Bolt4.1 C2.2 C4.2 C5.2 C9.2 C10.2 C15.2 C17.2 C18.2 C19.2 C21.1 C22.2 C24.2 C27.2 C28.2 C29.2 C31.2 C33.2 C34.2 C38.2 C39.2 C44.2 C46.2 C47.2 C48.2 C50.1 C51.2 C53.2 C56.2 C57.1 C58.2 D2.2 D3.2 D6.2 D7.1 D10.1 D11.1 D13.2 D14.2 D17.2 D18.1 D19.2 D20.2 J1.2 J2.2 J3.4 J3.16 J3.19 J3.20 J3.23 J3.24 J3.26 J4.3 J4.6 J4.7 J4.8 J4.9 J4.10 L4.1 L10.1 R24.1 R48.1 R53.1 R54.1 RL1.2 RL2.2 U1.2 U1.4 U2.3 U3.3 U4.3 U6.3 U7.2 U7.4 U8.3 U9.3 U10.3 U12.3 U13.5 X10.1 | length 11539.7
  Top Layer w12: v1(2700,5275) 2725,5300 U10.3 ; U9.3 2900,4575 2925,4550 v1(2925,4425) ; C56.2 3425,6000 3400,6025 3400,6100 U12.3 ; C47.2 3850,6100 U8.3 ; C18.2 4400,6100 U2.3 ; C27.2 4875,5975 4850,6000 4850,6100 U6.3 ; v1(5275,4535) 5315,4575 U3.3 ; 5350,5150 5350,5275 5375,5300 U4.3
  Top Layer w15: RL2.2 4165,4690 v2(4200,4725) ; v2(4800,4750) 4815,4735 RL1.2
  Top Layer w25: U13.5 C57.1
  Top Layer w30: C50.1 2493.24,5950 C53.2 ; D17.2 2675,3875 2934.25,3615.75 L10.1 ; v1(2700,6675) 2794.49,6675 D13.2 2930.51,6680.51 2950,6700 D14.2 ; R48.1 v1(3100,5950) ; C51.2 v1(3075,6400) ; C39.2 v1(3175,5525) ; C34.2 v1(3250,6725) ; v1(3350,5925) 3375,5950 C56.2 ; v1(3425,7175) C29.2 ; C48.2 v1(3875,6350) ; v1(3825,5850) 3850,5875 C47.2 ; v1(4200,6350) C33.2 ; v1(4375,5875) 4400,5900 C18.2 ; C28.2 4530,7170 4530,7139.3 J3.16 ; D10.1 4675,7350 4700,7375 v1(4775,7375) X10.1 ; v1(4725,6350) C4.2 ; v1(4850,5875) 4875,5900 C27.2 ; v1(5275,4535) D7.1 5280.51,4425 C15.2 ; v1(5325,5150) 5350,5150 C17.2 ; D3.2 5554.33,6901.18 5575,6880.51 5575,6625 C5.2 ; v2(5450,7375) R53.1 R54.1 ; L4.1 5453.75,3446.25 5480,3420 5620,3420 5675,3475 D6.2 ; 5700,6600 5800,6600 5825,6575 R24.1 5950,6500 5975,6475 5975,6325 5950,6300 C22.2 ; C24.2 v1(5850,5950) ; C9.2 v1(5925,4725) ; C10.2 5925,5450 v1(5950,5475)
  Top Layer w40: v1(2700,5275) 2700,5200 C46.2 ; C44.2 v1(2925,4425) ; C38.2 v1(3225,4725) ; D18.1 3330.51,4194.49 v1(3400,4125) ; D20.2 3725,4400 v2(3775,4350) ; J2.2@3744,3475 3950,3475 4000,3525 C31.2 ; D11.1 v1(3875,7325) ; v2(4250,4450) 4344.49,4450 D19.2 ; J1.2@4944,3475 5100,3475 5175,3550 C2.2 ; C19.2@5250,6350 5300,6350 v1(5325,6375) ; 5575,6625 v2(5625,6625) 5675,6625 5700,6600 ; 5975,6325 C58.2 ; v2(6400,6450) C57.1
  Dummy Ground w15: J3.26@3319,6987.81 3319,7069 v1(3425,7175) 3425,7150 3450.5,7124.5 4625.5,7124.5 ; J3.4 4571,6989.31 J3.16 4625.5,7124.5 ; J3.26@5169,6987.81 5032.3,7124.5 4625.5,7124.5
NetC1_2: C1.2 U1.1 | length 143
  Top Layer w25: U1.1 C1.2
NetC3_1: C3.1 L1.1 U1.3 | length 303.4
  Top Layer w20: C3.1 C3.1@4850,3750 ; U1.3 C3.1@4850,3750 ; L1.1 C3.1@4850,3750
NetC3_2: C3.2 J1.1 X2.1 | length 513.9
  Top Layer w20: C3.2 4844,3606 J1.1 X2.1
NetC6_1: C6.1 R5.1 R8.2 R11.2 R49.1 U3.2 | length 1470.3
  Top Layer w12: R5.1@5425,4825 R5.1@5575,4825 ; U3.2 5575,4625 ; C6.1 R49.1 R5.1@5575,4825 ; R8.2 R11.2 5725,4275 5600,4400 5600,4600 5575,4625 ; 5575,4625 5600,4650 5600,4725 5575,4750 R5.1@5575,4825
NetC6_2: C6.2 R5.2 R9.1 R12.1 R49.2 U3.6 X5.1 | length 1253.9
  Top Layer w12: U3.6 5675,4575 5650,4600 5650,4725 5675,4750 R5.2@5675,4825 ; R5.2@5825,4825 R5.2@5675,4825 ; R12.1 R9.1 X5.1 5725,5150 5675,5100 C6.2 R49.2 R5.2@5675,4825
NetC7_1: C7.1 R50.2 | length 100
  Top Layer w12: R50.2 C7.1
NetC7_2: C7.2 R4.1 R6.2 R13.1 U2.5 U4.6 X4.1 | length 2366.9
  Top Layer w12: R13.1 4350,6000 4325,5975 4325,5825 4350,5800 4575,5800 X4.1 4675,5825 ; U2.5 4700,6037.5 R4.1 4700,5850 4675,5825 ; U4.6 5675,5300 5650,5325 5650,5425 5675,5450 R6.2 C7.2 5675,5675 5625,5725 4775,5725 4675,5825
NetC8_1: C8.1 R3.1 R4.2 U2.6 | length 733.2
  Top Layer w12: R3.1 C8.1 4550,6375 4575,6350 4575,6125 4600,6100 ; R4.2 4600,6100 ; U2.6 4600,6100
NetC8_2: C8.2 R7.1 U2.7 | length 518.6
  Top Layer w12: R7.1 C8.2 4650,6400 4600,6350 4600,6175 4625,6150 U2.7
NetC11_1: C11.1 C14.1 D4.2 D6.1 L2.1 L4.2 R8.1 | length 2752.5
  Top Layer w12: L2.1 v1(5325,4750) ; R8.1 6151.57,4050 ; C11.1 6151.57,4050 ; C14.1 6151.57,4050
  Top Layer w20: L4.2 5553.75,3641.25 5475,3720 D4.2 5544.49,3855.51 5575,3886.02 5575,4025 5600,4050 R8.1
  Bottom Layer w12: v1(5325,4750) 5625,4450 C14.1
NetC11_2: C11.2 C14.2 R11.1 | length 965.8
  Top Layer w12: R11.1 6025,4475 6075,4525 6300,4525 6348.43,4476.57 C14.2 C11.2
NetC12_1: C12.1 C16.1 R12.2 | length 798.4
  Top Layer w12: R12.2 6348.43,5375 ; C16.1 6348.43,5375 ; C12.1 6348.43,5375
NetC12_2: C12.2 C16.2 R6.1 R9.2 R50.1 U4.2 | length 1851.9
  Top Layer w12: U4.2 5425,5350 v2(5400,5375) 5400,5475 5425,5500 R50.1 R6.1 ; R9.2 6125,5050 6151.57,5023.43 C16.2
  Bottom Layer w12: v2(5400,5375) 5425,5400 6000,5400 6050,5450 C12.2 C16.2
NetC13_1: C13.1 R10.1 R13.2 U2.2 | length 651.8
  Top Layer w12: R13.2 U2.2 4525,6150 4550,6175 4550,6275 4450,6375 C13.1 R10.1
NetC13_2: C13.2 R14.1 U2.1 | length 421.6
  Top Layer w12: R14.1 C13.2 4350,6400 4462.5,6287.5 U2.1
NetC20_1: C20.1 R15.1 R16.1 U5.2 | length 926.8
  Top Layer w12: R15.1 5525,6150 U5.2 5700,6150 v1(5725,6125) ; R16.1 C20.1 v1(6175,6200)
  Bottom Layer w12: v1(5725,6125) 6100,6125 v1(6175,6200)
NetC20_2: C20.2 R16.2 R18.1 R22.1 U5.6 U6.5 X7.1 | length 2125.5
  Top Layer w12: R22.1 4800,5825 4825,5800 5150,5800 5175,5825 ; U6.5 5137.5,6037.5 5175,6000 R18.1 5175,5825 ; U5.6 R16.2 ; C20.2 R16.2 ; 5175,5825 5200,5800 5875,5800 5975,5900 R16.2
NetC21_2: C21.2 R15.2 | length 105.9
  Top Layer w12: C21.2 5398.33,6173.33 R15.2
NetC23_1: C23.1 R17.1 R18.2 U6.6 | length 739.3
  Top Layer w12: R17.1 C23.1 4950,6325 5025,6250 5025,6150 5075,6100 ; R18.2 5075,6100 ; U6.6 5075,6100
NetC23_2: C23.2 R19.1 U6.7 | length 497.9
  Top Layer w12: R19.1 C23.2 5050,6175 5075,6150 U6.7
NetC25_2: C25.2 R20.1 R24.2 U5.3 | length 1186.8
  Top Layer w12: U5.3 5575,6100 5500,6025 5500,6000 5475,5975 5350,5975 5325,6000 5325,6225 5401.57,6301.57 C25.2 5501.57,6301.57 5600,6400 R20.1 R24.2
NetC26_1: C26.1 R21.1 R22.2 U6.2 | length 672.5
  Top Layer w12: R22.2 U6.2 4975,6150 5000,6175 5000,6225 4925,6300 4925,6400 C26.1 R21.1
NetC26_2: C26.2 R23.1 U6.1 | length 486.2
  Top Layer w12: R23.1 C26.2 4750,6425 4775,6400 4850,6400 4875,6375 4875,6275 4912.5,6237.5 U6.1
NetC28_1: C28.1 D8.2 D10.2 L5.2 | length 505.2
  Top Layer w20: L5.2 4450,7250 4480.51,7250 ; D10.2 4480.51,7250 ; D8.2 4625,7200 4625,7250 4480.51,7250
NetC29_1: C29.1 D9.1 D11.2 L6.2 | length 708.4
  Top Layer w50: D9.1 D11.2 3600,7305.51 C29.1 3800,7175 3825,7200 L6.2
NetC30_2: C30.2 U7.1 | length 143
  Top Layer w25: U7.1 C30.2
NetC32_1: C32.1 L7.1 U7.3 | length 328.4
  Top Layer w25: U7.3 C32.1 3675,3750 L7.1
NetC32_2: C32.2 J2.1 X12.1 | length 508.5
  Top Layer w25: C32.2 3650,3381 J2.1 X12.1
NetC35_1: C35.1 R29.1 R32.2 R35.2 R51.1 U9.2 | length 912.5
  Top Layer w12: R35.2 2725,4625 ; U9.2 2725,4625 ; C35.1 R51.1 2875,4825 2725,4825 2725,4625
  Top Layer w40: R32.2 R35.2
NetC35_2: C35.2 R29.2 R33.1 R36.1 R51.2 U9.6 X15.1 | length 1410
  Top Layer w12: R36.1 R33.1 2625,5075 2650,5050 ; X15.1 2650,5050 ; U9.6 2975,4575 2950,4600 2950,4725 2975,4750 ; R29.2@3125,4825 3050,4750 2975,4750 ; 2650,5050 2675,5075 2975,5075 C35.2 R51.2 2975,4825 2975,4750
NetC36_1: C36.1 R52.2 | length 100
  Top Layer w12: R52.2 C36.1
NetC36_2: C36.2 R28.1 R30.2 R37.1 U8.5 U10.6 X14.1 | length 2324.3
  Top Layer w12: U10.6 2975,5300 2950,5325 2950,5425 2975,5450 R30.2 C36.2 2975,5675 3025,5725 3675,5725 3775,5825 ; R37.1 3800,5900 3775,5875 3775,5825 ; U8.5 4200,6050 4200,5950 ; R28.1 4200,5950 ; 3775,5825 3800,5800 4025,5800 X14.1 4175,5825 4200,5850 4200,5950
NetC37_1: C37.1 R27.1 R28.2 U8.6 | length 733.2
  Top Layer w12: R28.2 4050,6100 ; R27.1 C37.1 4050,6375 4025,6350 4025,6125 4050,6100 ; U8.6 4050,6100
NetC37_2: C37.2 R31.1 U8.7 | length 539.3
  Top Layer w12: U8.7 4075,6150 4050,6175 4050,6325 4150,6425 C37.2 R31.1
NetC40_1: C40.1 C43.1 D15.2 D17.1 L8.1 L10.2 R32.1 | length 3009.8
  Top Layer w40: C43.1 2201.57,4350 ; C40.1 2201.57,4350 ; R32.1 2550,4350 ; L10.2 3034.25,3690.75 2900,3825 D15.2 2819.49,4005.51 2800,4025 2800,4150 2755.51,4194.49 ; L8.1 3425,4425 3325,4325 2850,4325 2755.51,4230.51 2755.51,4194.49 ; 2201.57,4350 2550,4350 ; 2550,4350 2550,4225 2580.51,4194.49 D17.1 2755.51,4194.49
NetC40_2: C40.2 C43.2 R35.1 | length 771.4
  Top Layer w40: C40.2 2398.43,4573.43 2450,4625 R35.1
  Bottom Layer w40: C43.2 C40.2
NetC41_1: C41.1 C45.1 R36.2 | length 798.4
  Top Layer w12: C45.1 2201.57,5300 ; C41.1 2201.57,5300 ; R36.2 2201.57,5300
NetC41_2: C41.2 C45.2 R30.1 R33.2 R52.1 U10.2 | length 1354.9
  Top Layer w12: C45.2 R33.2 ; C41.2 2550,5450 2650,5350 U10.2 2850,5350 2875,5375 R30.1 R52.1
  Bottom Layer w12: C45.2 C41.2
NetC42_1: C42.1 R34.1 R37.2 U8.2 | length 595.7
  Top Layer w12: R37.2 U8.2 3950,6150 3975,6175 3975,6450 C42.1 R34.1
NetC42_2: C42.2 R38.1 U8.1 | length 425.9
  Top Layer w12: R38.1 C42.2 3850,6425 3875,6400 3900,6400 3925,6375 3925,6212.5 U8.1
NetC49_1: C49.1 R39.1 R40.1 U11.2 | length 903.9
  Top Layer w30: v1(2700,6250) R39.1 2750,6175 2775,6150 U11.2 ; v1(3150,6325) R40.1 C49.1
  Bottom Layer w30: v1(2700,6250) 2800,6250 2875,6325 v1(3150,6325)
NetC49_2: C49.2 R40.2 R42.1 R46.1 U11.6 U12.5 X17.1 | length 1271.2
  Top Layer w30: U11.6 R40.2 C49.2 3250,6050 ; R46.1 3250,6050 ; U12.5 3687.5,6037.5 3725,6000 R42.1 3725,5850 3700,5825 X17.1 3575,5825 3525,5775 3400,5775 3250,5925 3250,6050
NetC50_2: C50.2 R39.2 | length 260
  Top Layer w30: C50.2 2565.09,6075 R39.2
NetC52_1: C52.1 R41.1 R42.2 U12.6 | length 760
  Top Layer w12: 3625,6100 3575,6150 3575,6325 3650,6400 C52.1 R41.1
  Top Layer w30: R42.2 3625,6000 3600,6025 3600,6075 3625,6100 U12.6
NetC52_2: C52.2 R43.1 U12.7 | length 560
  Top Layer w12: U12.7 3625,6150 3600,6175 3600,6275 3750,6425 C52.2 R43.1
NetC54_2: C54.2 R44.1 R48.2 U11.3 | length 814.1
  Top Layer w30: C54.2 2787.23,6412.01 2900,6412.01 ; U11.3 2896,6100 2898,6102 ; R48.2 2925,6075 2898,6102 ; R44.1 2937.01,6412.01 2900,6412.01 ; 2898,6102 2898,6248.54 2900,6250.54 2900,6412.01
NetC55_1: C55.1 R45.1 R46.2 U12.2 | length 610.4
  Top Layer w12: R46.2 U12.2 3525,6150 3550,6175 C55.1
  Top Layer w30: C55.1 R45.1
NetC55_2: C55.2 R47.1 U12.1 | length 380.2
  Top Layer w30: R47.1 C55.2 3450,6375 3462.5,6362.5 U12.1
NetD4_K: D4.1 D5.2 | length 359.7
  Top Layer w40: D5.2 5344.49,3855.51 5375,3886.02 5375,4025 5394.49,4044.49 D4.1
NetD5_K: D5.1 D7.2 | length 186
  Top Layer w40: D5.1 D7.2
NetD15_K: D15.1 D16.2 | length 336.9
  Top Layer w40: D15.1 2955.51,4194.49 3000,4150 3000,4050 3044.49,4005.51 D16.2
NetD16_K: D16.1 D18.2 | length 331.1
  Top Layer w40: D16.1 3105.51,4200 3150,4200 3200,4150 3200,4025 3219.49,4005.51 D18.2
NetL1_2: L1.2 R2.1 | length 125
  Top Layer w20: L1.2 R2.1
NetL7_2: L7.2 R26.1 | length 125
  Top Layer w25: L7.2 R26.1
NetR1_1: R1.1 RL1.6 X1.1 | length 520.1
  Top Layer w25: RL1.6 4905,4580 4975,4650 X1.1 4975,4875 R1.1
NetR25_1: R25.1 RL2.6 X11.1 | length 860.4
  Top Layer w25: R25.1 3625,4900 X11.1 3825,4875 3875,4825 3950,4825 4025,4750 4025,4600 4045,4580 RL2.6
OUT1+: J3.9 R3.2 R7.2 | length 834.9
  Top Layer w30: v2(4550,6750) R3.2 R7.2
  Bottom Layer w12: J3.9 4026,6899 4075,6850 4125,6850 4275,6700 4500,6700 v2(4550,6750)
OUT1-: J3.21 R10.2 R14.2 | length 650.4
  Top Layer w12: R14.2 v2(4350,6750)
  Top Layer w30: R14.2 R10.2
  Bottom Layer w8: 4080.5,6900 J3.21
  Bottom Layer w12: 4080.5,6900 4105.5,6875 4150,6875 4275,6750 v2(4350,6750)
OUT2+: J3.13 R27.2 R31.2 | length 752.4
  Top Layer w12: R27.2 v2(4050,6750)
  Top Layer w30: R27.2 R31.2
  Bottom Layer w12: J3.13 3590,6860 3625,6825 3975,6825 v2(4050,6750)
OUT2-: J3.25 R34.2 R38.2 | length 843.7
  Top Layer w12: R38.2 v2(3850,6750)
  Top Layer w30: R38.2 3900,6675 R34.2
  Bottom Layer w12: J3.25 3568.8,7043.81 3525,7000 3525,6850 3575,6800 3825,6800 3850,6775 v2(3850,6750)
PHOTODIODE1_PIN1: C1.1 D1.2 J4.5 L2.2 R1.2 | length 2293.4
  Top Layer w20: J4.5 4462,5412 4500,5450 4900,5450 4950,5400 4950,5225 4975,5200 5200,5200 L2.2 5100,4875 5075,4850 5075,4400 C1.1 ; R1.2 D1.2
PHOTODIODE1_PIN2: C5.1 C25.1 D1.1 D2.1 D3.1 J4.4 L3.2 R20.2 X6.1 | length 3934.6
  Top Layer w20: J4.4 4353,5403 4450,5500 5000,5500 5050,5450 D1.1 ; X6.1 5413.49,6550 ; D2.1@5575,7069.49 5555.51,7050 5400,7050 5375,7025 5375,6850 5425,6800 5425,6750 C5.1 5425,6561.51 5413.49,6550 ; R20.2 5463.49,6500 5413.49,6550
  Bottom Layer w20: J4.4 4353,5528 5325,6500 5463.49,6500 C25.1
PHOTODIODE2_PIN1: C30.1 D12.2 J4.2 L8.2 R25.2 | length 2344.3
  Top Layer w25: C30.1 3550,4675 3525,4700 L8.2 R25.2 D12.2 3415.55,5175 3350,5175 3350,5450 3400,5500 4075,5500 4135,5440 J4.2
PHOTODIODE2_PIN2: C34.1 C54.1 D12.1 D13.1 D14.1 J4.1 L9.2 R44.2 X16.1 | length 3518.1
  Top Layer w25: C54.1 2824.63,6548.3 2847.93,6525 R44.2 3050,6525 ; D13.1 3055.51,6869.49 L9.2 C34.1 X16.1 3075,6550 3050,6525 ; v2(3325,6500) 3075,6500 3050,6525 ; D12.1 3425,5425 3450,5450 3975,5450 4026,5399 J4.1
  Bottom Layer w25: v2(3325,6500) 3625,6200 3625,5950 4026,5549 J4.1
RLY1: D19.1 J3.18 RL1.1 | length 5387.4
  Top Layer w25: D19.1 4384.49,4660 RL1.1 ; RL1.1@4560,4660 4575,4675 v2(4575,4775)
  Bottom Layer w25: J3.18 4407.5,7082.5 4500,7175 5400,7175 5900,6675 6050,6675 6375,6350 6375,5900 6025,5550 5375,5550 4600,4775 v2(4575,4775)
RLY2: D20.1 J3.22 RL2.1 | length 3461.8
  Top Layer w25: v2(3750,4800) 3725,4775 D20.1 3875.51,4669.49 RL2.1
  Bottom Layer w25: v2(3750,4800) 3750,4825 3525,5050 3525,6075 3300,6300 3300,6375 3275,6400 3275,6600 3481.3,6806.3 3481.3,7056.3 3575,7150 3943,7150 3971.5,7121.5 J3.22
TEST+: J3.2 R53.2 U13.3 | length 1977.8
  Top Layer w12: J3.2 4844.5,6987.31 4937.31,6987.31 5125,7175 5500,7175 5550,7225 ; R53.2 5550,7225 ; U13.3 5900,6575 5825,6650 5725,6650 5675,6700 5675,7150 5650,7175 5600,7175 5550,7225
TEST-: J3.14 R54.2 U13.2 | length 2333
  Top Layer w12: J3.14 4943.81,7043.81 5100,7200 5325,7200 5375,7250 5375,7400 5425,7450 5700,7450 5725,7425 5725,7300 5700,7275 R54.2 5650,7225 5700,7175 5700,6725 5750,6675 5850,6675 5900,6625 U13.2
TESTSIG: RL1.5 RL2.5 U13.6 | length 5144.6
  Top Layer w25: RL2.5 3885,4440 3950,4375 4500,4375 4535,4410 v2(4535,4450) RL1.5 ; U13.6 6225,6575 6200,6550 6200,6500 6325,6375 v2(6325,5725)
  Bottom Layer w25: v2(4535,4450) 5050,4450 5175,4325 6200,4325 6250,4375 6250,5650 v2(6325,5725)
pads on no net: J3.1 U3.1 U3.5 U3.8 U4.1 U4.5 U4.8 U5.1 U5.5 U5.8 U9.1 U9.5 U9.8 U10.1 U10.5 U10.8 U11.1 U11.5 U11.8 U13.1 U13.8

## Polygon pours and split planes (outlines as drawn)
GND on Bottom Layer "Top Layer-No Net" (solid, remove dead copper, shelved, pour order 0): 2025,3025 6450,3025 6450,7450 2025,7450
GND on Dummy Ground "Top Layer-No Net" (solid, remove dead copper, shelved, pour order 2): 2025,7450 6450,7450 6450,3025 2025,3025
-15VIN on Dummy Power "Top Layer-No Net" (solid, shelved, pour order 14): 3475,6600 4400,6600 4400,7525 3475,7525
+15VIN on Dummy Power "Top Layer-No Net" (solid, remove dead copper, shelved, pour order 12): 3495,6625 3495,7500 4390,7500 4390,6635 4385,6630
+15V on Dummy Power "Top Layer-No Net" (solid, remove dead copper, shelved, pour order 6): 2025,7450 6450,7450 6450,3025 2025,3025
-15V on Dummy Power "Top Layer-No Net" (solid, remove dead copper, shelved, pour order 4): 2025,7450 6450,7450 6450,3025 2025,3025
GND on Top Layer "Top Layer-GND" (solid, remove dead copper, shelved, pour order 8): 2025,3025 6475,3025 6475,7475 2025,7475

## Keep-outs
Keep-Out Layer:
  lines w10: 2000,3594 ccw(c2594,3594) 2594,3000 5894,3000 ccw(c5894,3594) 6488,3594 6488,6894 ccw(c5894,6894) 5894,7488 2594,7488 ccw(c2594,6894) 2000,6894 2000,3594

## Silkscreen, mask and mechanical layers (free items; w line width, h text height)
Top Overlay:
  lines w10: 3790,5905 3790,6005 ; 3800,3800 3830,3830 ; 5010,3790 5010,3800 5030,3820 ; 5810,6025 5850,5985 5880,5985
Mechanical 2:
  lines w10: 2000,3595 2000,3710 ; 2000,3709 2709,3709 2709,3000 ; 2000,6779 2709,6779 2709,7488 ; 2000,6780 2000,6890 ; 2595,3000 2710,3000 ; 2595,7488 2710,7488 ; 5779,3000 5779,3709 6488,3709 ; 5779,7488 5779,6779 6488,6779 ; 5780,3000 5895,3000 ; 5780,7488 5892,7488 ; 6488,3595 6488,3710 ; 6488,6780 6488,6890 ; 3535,4890 4953,4890 4953,5598 3535,5598 3535,4890
Mechanical 3:
  rectangle: 2000,3944 6488,6544
Mechanical 4:
  lines w10: 2594,7488 ccw(c2594,6894) 2000,6894 2000,3594 ccw(c2594,3594) 2594,3000 5894,3000 ccw(c5894,3594) 6488,3594 6488,6894 ccw(c5894,6894) 5894,7488 2595,7488
Mechanical 10:
  lines w20: 4075,6000 5625,6000 5675,5950 5675,5825 5600,5750 3100,5750 3075,5725 3075,5300 3100,5275 3300,5275 3550,5525 5600,5525 5650,5475 5650,4900 5600,4850 3075,4850 3050,4825 3050,4625 3100,4575 5550,4575 5575,4550 5575,4475 5375,4275 3675,4275 3400,4000 3400,3050 3500,2950 6475,2950 6550,3025 6550,6175 6425,6300 6175,6300 6100,6375 6100,6525 6150,6575 6525,6575 ; 4125,6000 2925,6000 2825,6100 2825,6425 3000,6600 3475,6600 ; 4395,7185 4300,7185 4155,7330 3970,7330 3750,7110 3750,6875 3975,6875 3975,6975 3975,6980 3985,6990 4175,6990 4190,6975 4190,6875 4200,6865 4400,6865 ; 3475,6600 3475,7525 4400,7525 4400,6600 3475,6600
Mechanical 11:
  lines w10: 2728.35,3019.68 2728.35,7468.5 ; 2728.35,3748.03 5759.84,3748.03 ; 2728.35,6740.16 5759.84,6740.16 ; 5759.84,3019.68 5759.84,7468.5
Mechanical 16:
  lines w10: 3475,4000 3475,3925 3825,3925 3825,4000 ; 3475,4050 3475,4125 3825,4125 3825,4050 ; 4675,4000 4675,3925 5025,3925 5025,4000 ; 4675,4050 4675,4125 5025,4125 5025,4050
